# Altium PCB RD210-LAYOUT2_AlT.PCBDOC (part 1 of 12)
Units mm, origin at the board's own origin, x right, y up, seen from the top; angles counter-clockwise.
Board outline 250 x 123 mm, 4 copper layers (TOP, Mid-Layer 1, Mid-Layer 2, BOTTOM), stack 0.711 mm thick; 1043 components, 659 nets, 2786 pads, 1228 vias.
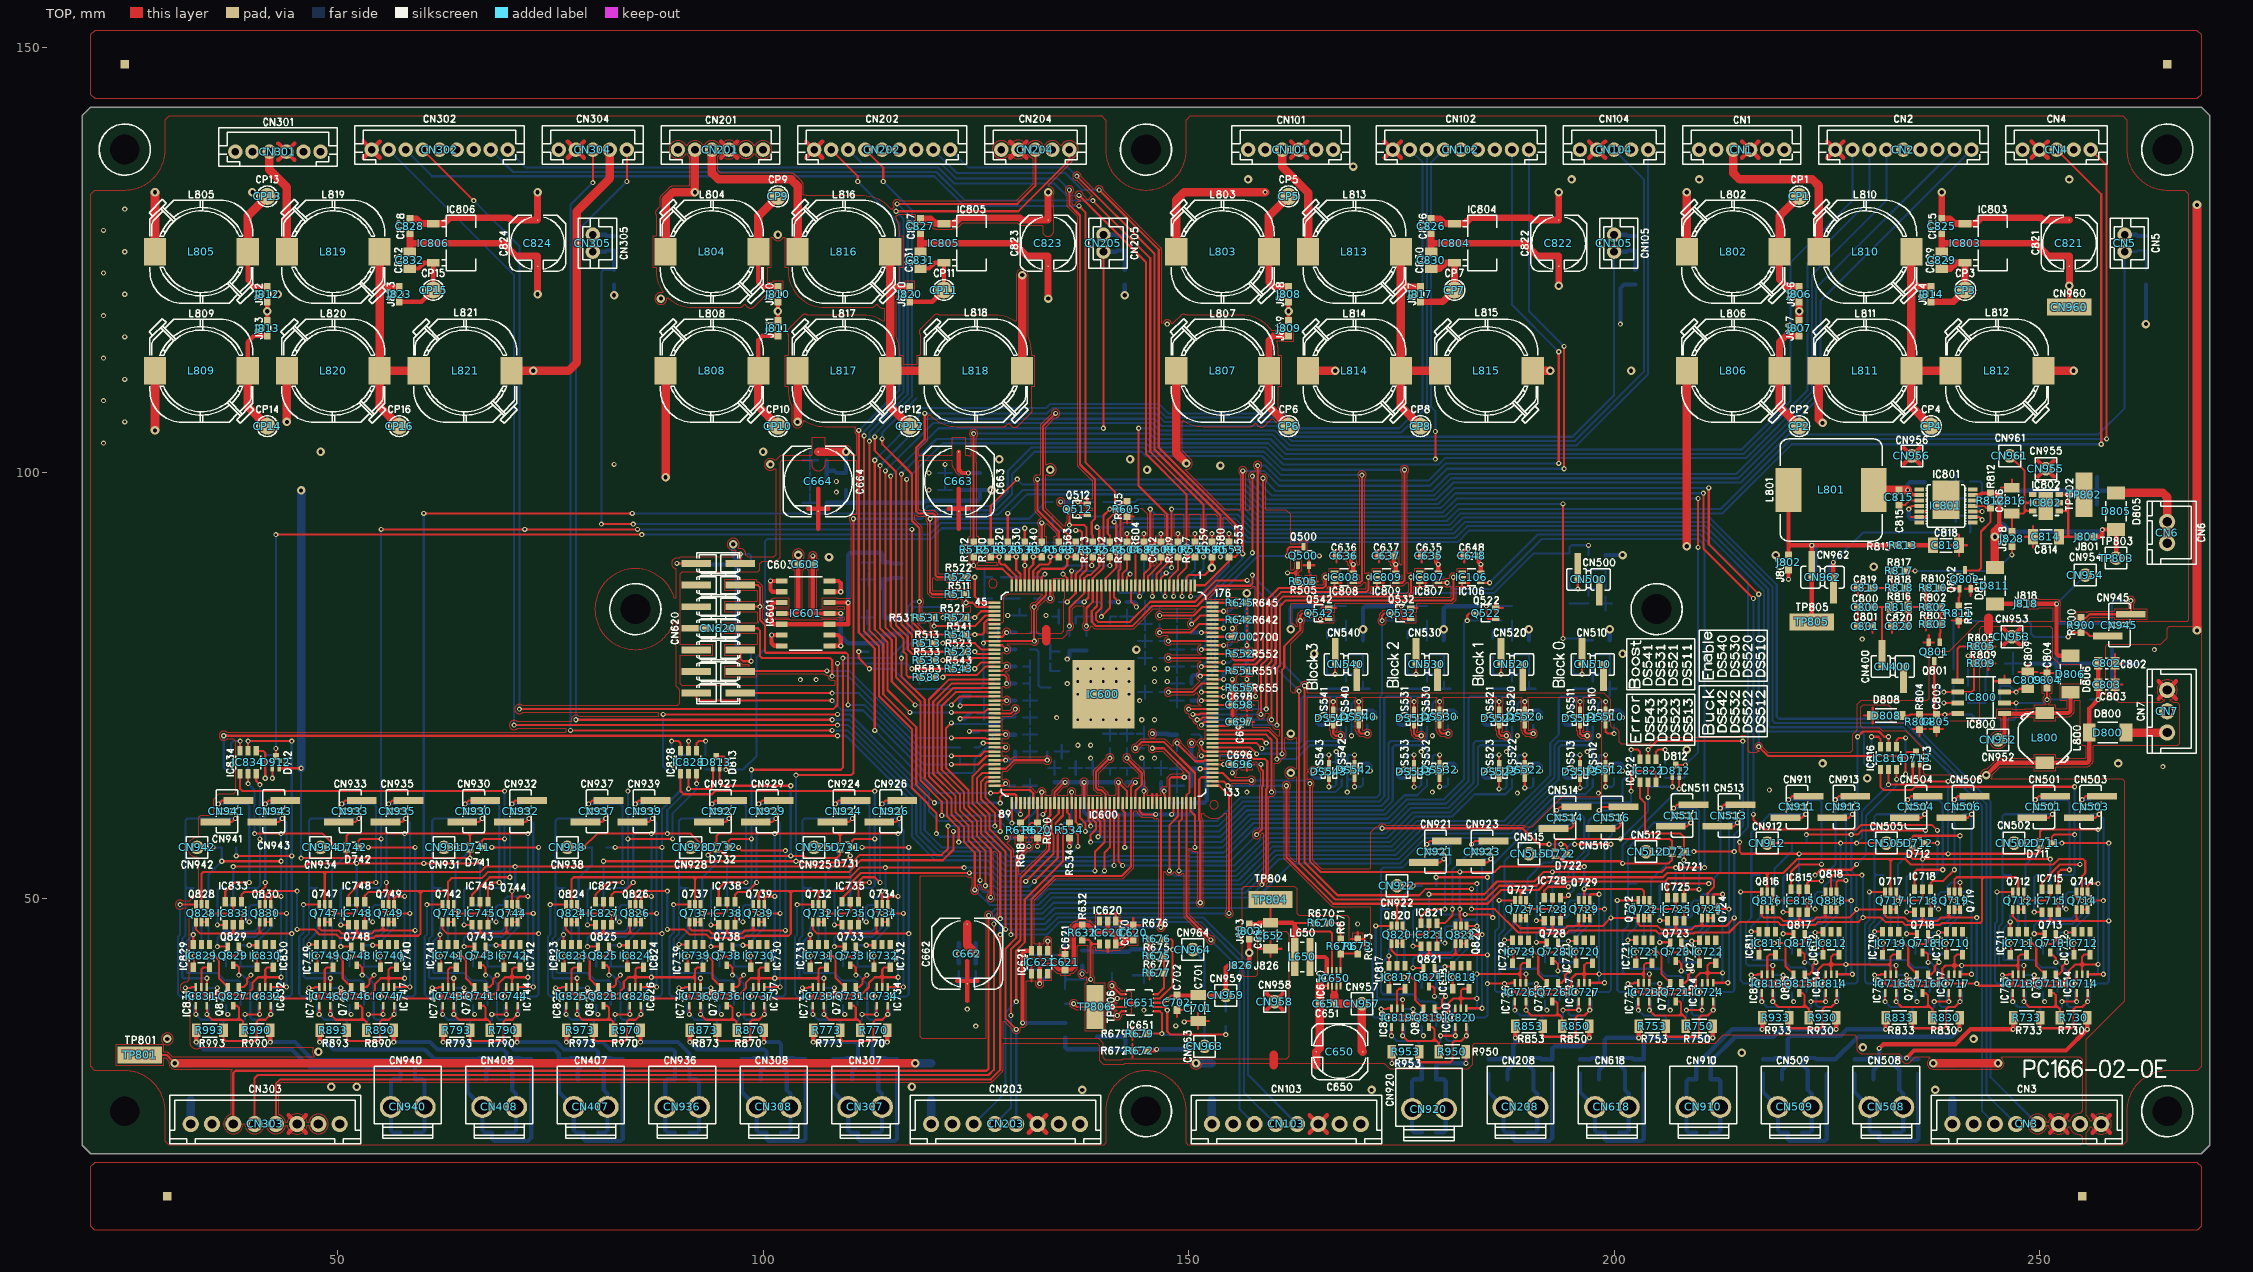
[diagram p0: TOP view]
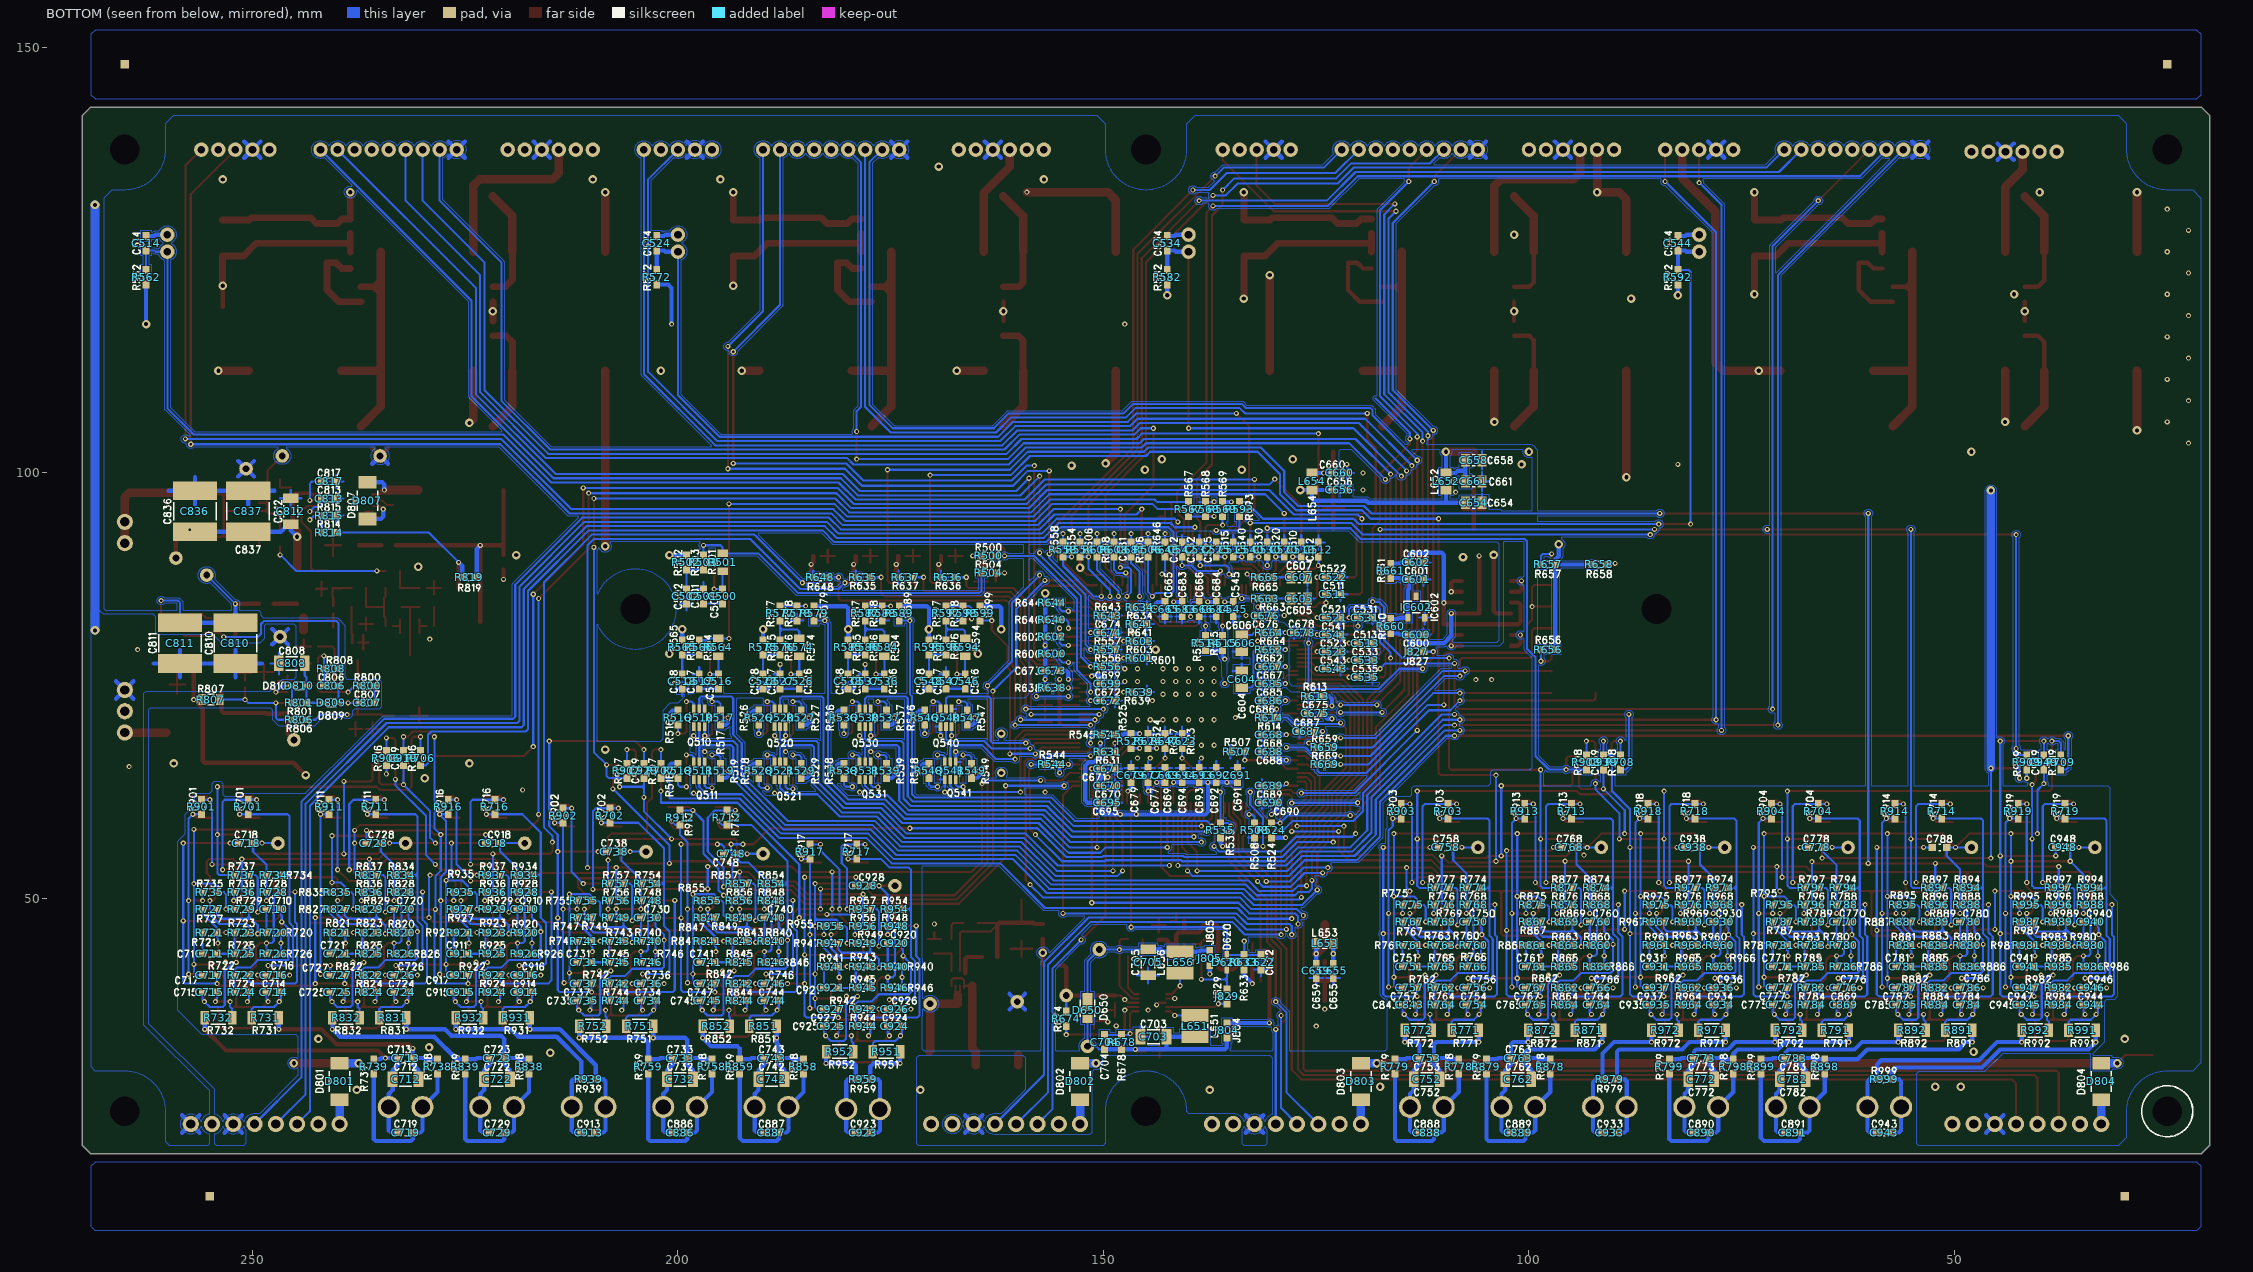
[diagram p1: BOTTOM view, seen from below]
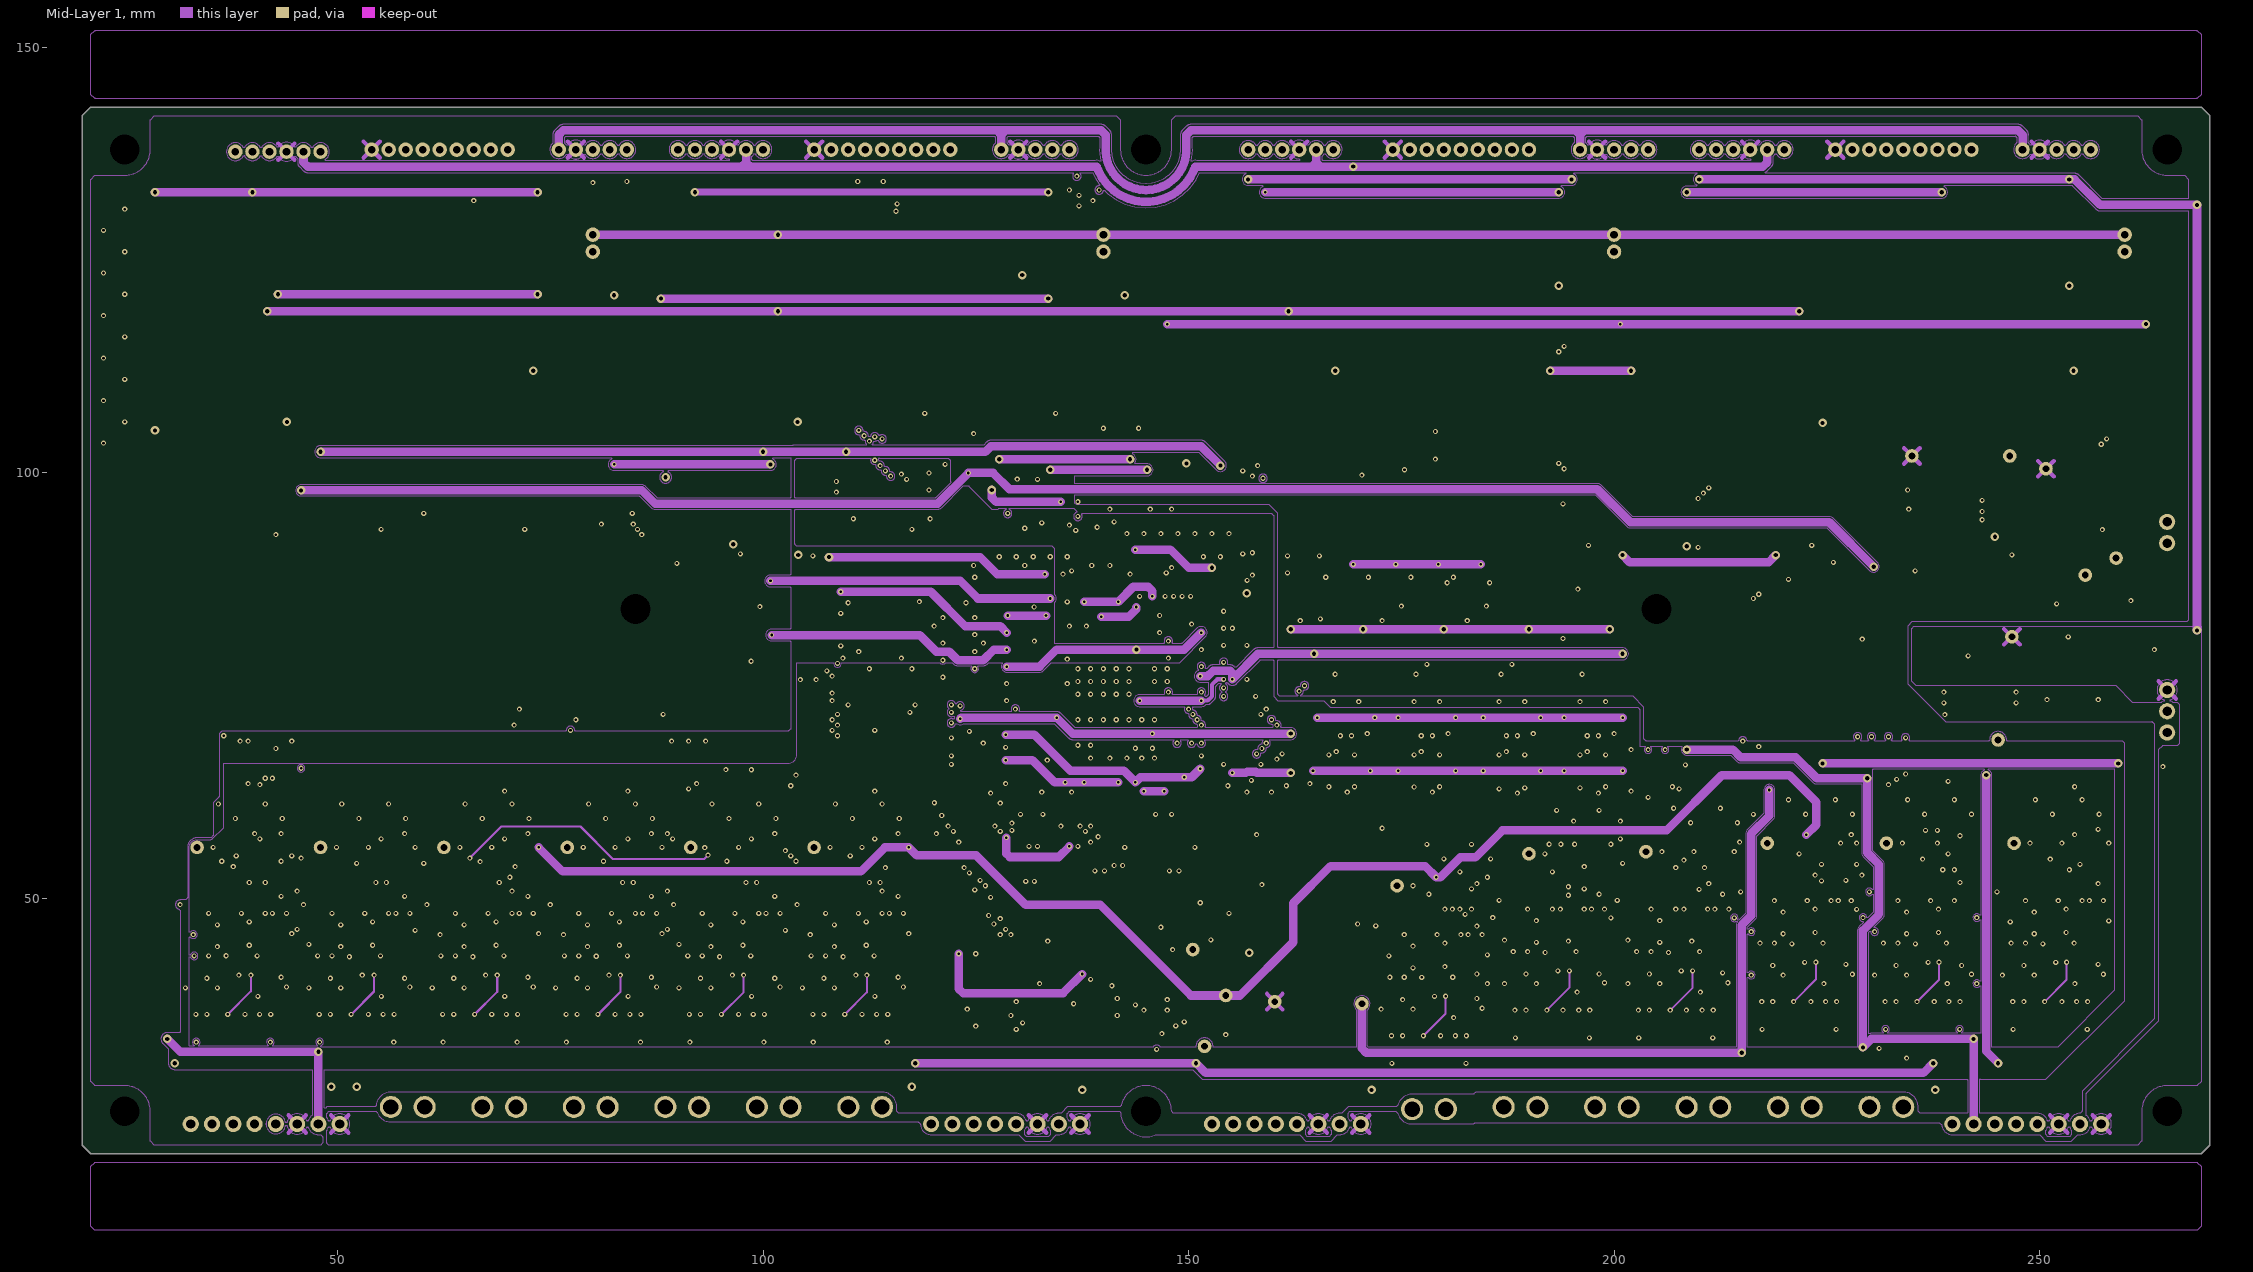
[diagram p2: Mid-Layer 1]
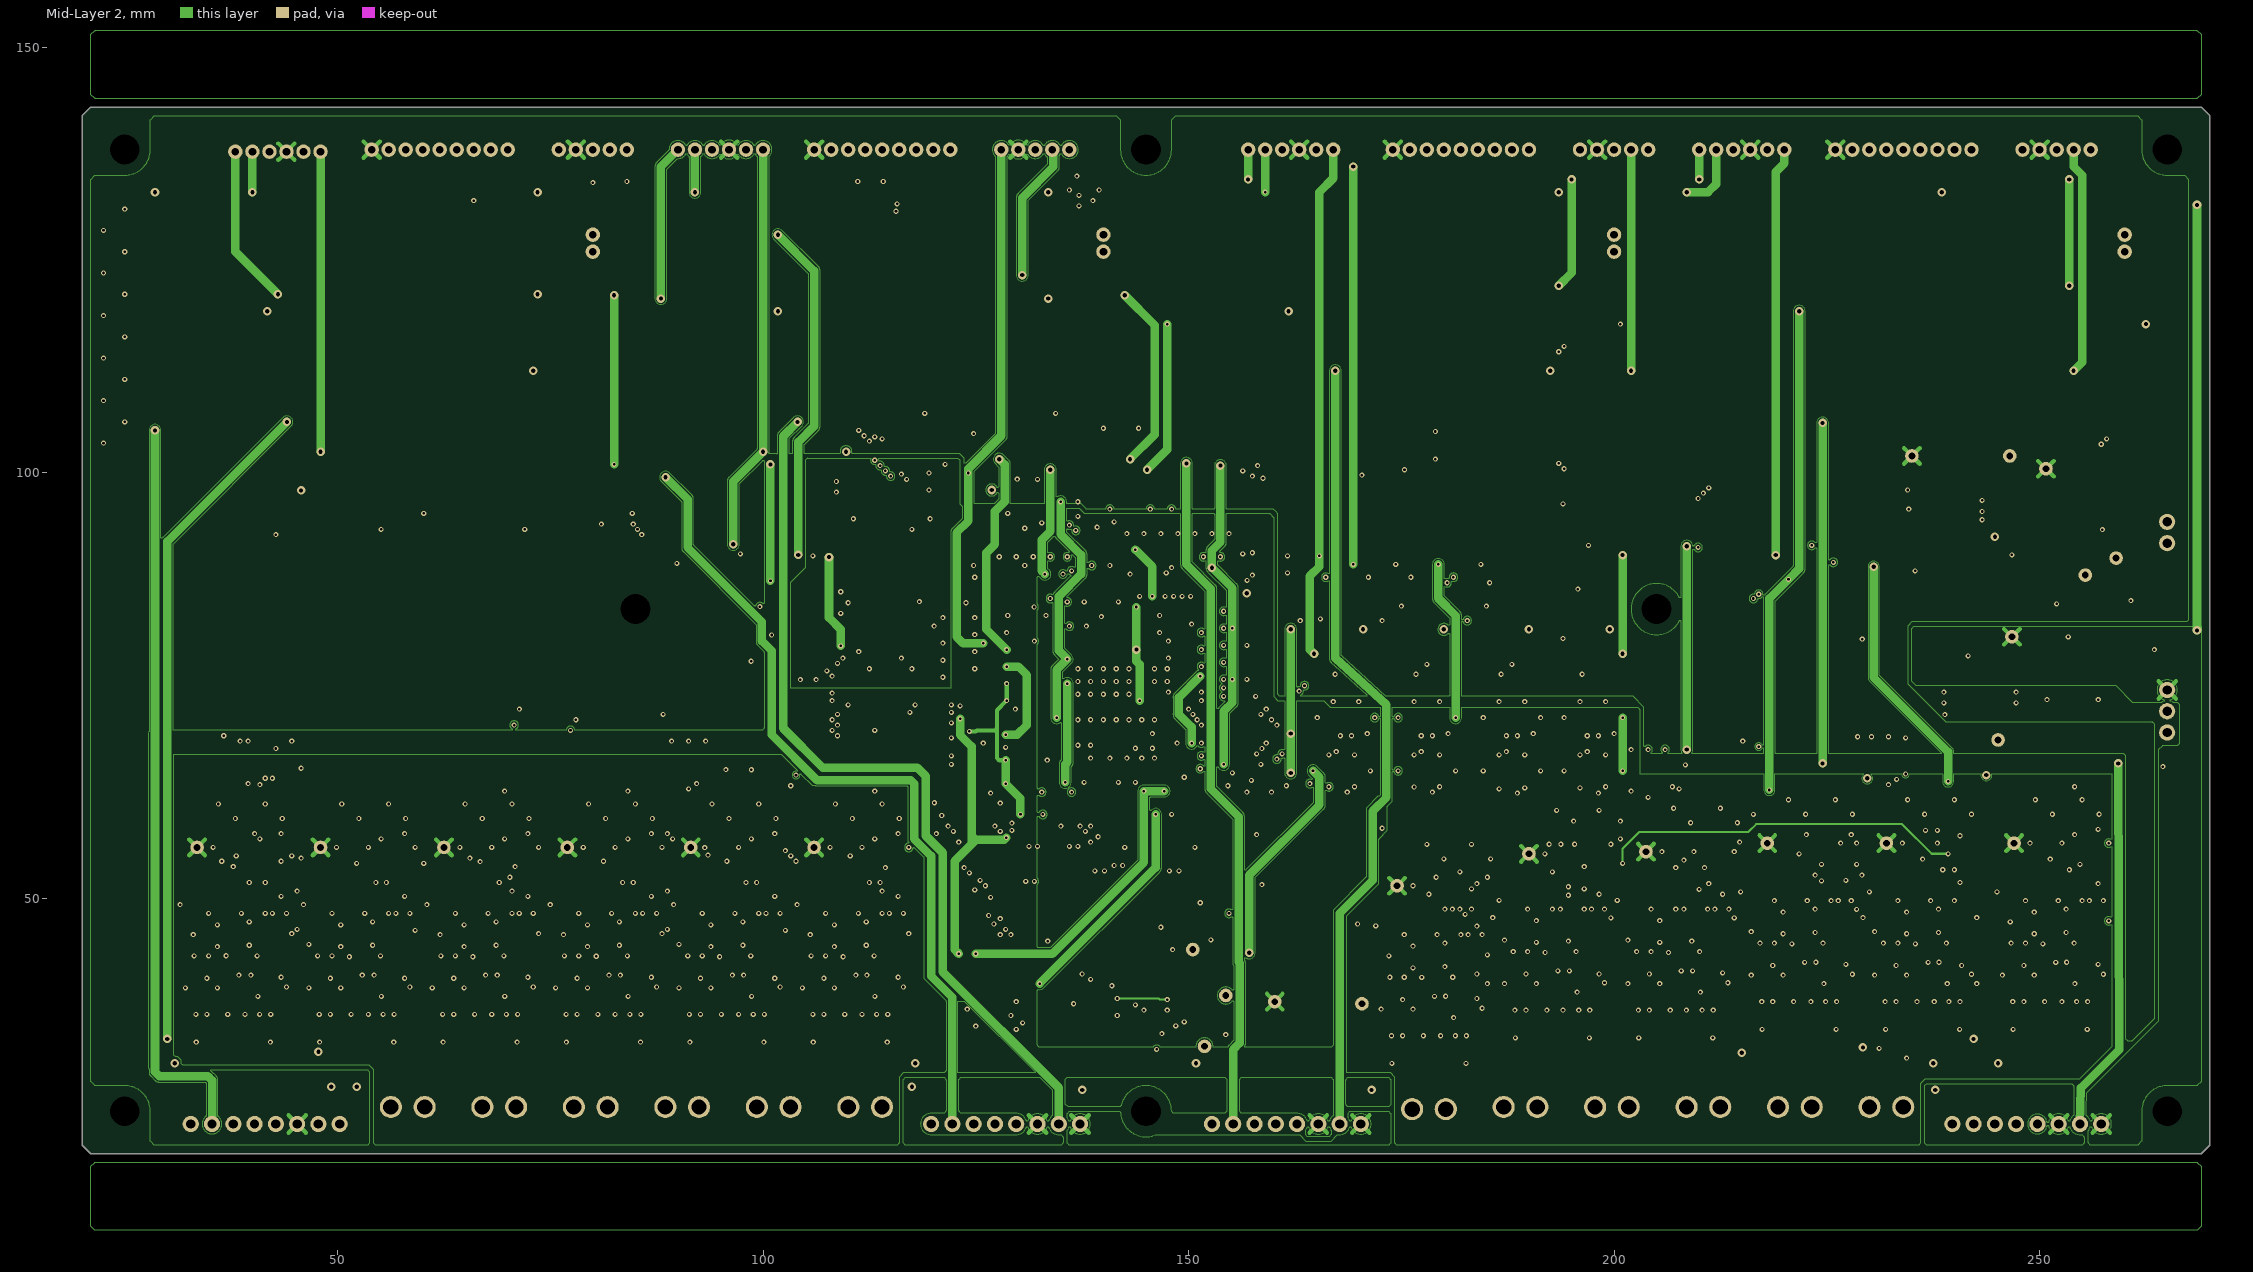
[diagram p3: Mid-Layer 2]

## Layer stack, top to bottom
Top Solder: solder mask 0.0102, Solder Resist, Dk 3.5
TOP: signal copper (thickness not stored)
Mid-Layer 1: signal copper 0.0356
Dielectric2: dielectric 0.32, FR-4, Dk 4.8
Mid-Layer 2: signal copper 0.0356
Dielectric3: dielectric 0.32, FR-4, Dk 4.8
BOTTOM: signal copper (thickness not stored)
Bottom Solder: solder mask 0.0102, Solder Resist, Dk 3.5

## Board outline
21,20 20,21 20,142 21,143 269,143 270,142 270,21 269,20

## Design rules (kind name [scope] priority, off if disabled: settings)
AssemblyTestPointUsage [All] p0: scope1count=1 scope1_0_kind=Board scope1_0_value=Board scope2count=1 scope2_0_kind=Board scope2_0_value=Board commentlength=0
AssemblyTestpoint [All] p0: scope1count=1 scope1_0_kind=Board scope1_0_value=Board scope2count=1 scope2_0_kind=Board scope2_0_value=Board commentlength=0
Clearance [All] p0: scope1count=1 scope1_0_kind=Board scope1_0_value=Board scope2count=1 scope2_0_kind=Board scope2_0_value=Board commentlength=0 gap=0.15
Clearance [All] p1: gap=0.15 ignorepadtopadclearanceinfootprint=TRUE except(0.3: Arc-Hole Track-Hole SMDPad-Hole THPad-Hole Via-Hole Fill-Hole Poly-Hole Region-Hole Text-Hole)
ComponentClearance [All] p0: scope1count=1 scope1_0_kind=Board scope1_0_value=Board scope2count=1 scope2_0_kind=Board scope2_0_value=Board commentlength=0 gap=0.254 collisioncheckmode=3
DiffPairsRouting [All] p0: scope1count=1 scope1_0_kind=Board scope1_0_value=Board scope2count=1 scope2_0_kind=Board scope2_0_value=Board commentlength=0
FabricationTestPointUsage [All] p0: scope1count=1 scope1_0_kind=Board scope1_0_value=Board scope2count=1 scope2_0_kind=Board scope2_0_value=Board commentlength=0 valid=0 allowmultiple=FALSE
FabricationTestpoint [All] p0: scope1count=1 scope1_0_kind=Board scope1_0_value=Board scope2count=1 scope2_0_kind=Board scope2_0_value=Board commentlength=0 side=3 testpointundercomponent=TRUE minsize=1.016 maxsize=2.54 preferedsize=1.524 minholesize=0 maxholesize=1.016 preferedholesize=0.813 testpointgrid=0.025
FanoutControl Fanout_BGA [All] p0 off: scope1count=1 scope1_0_kind=Board scope1_0_value=Board scope2count=1 scope2_0_kind=Board scope2_0_value=Board commentlength=69 // Protel DXP Scope 1 Expression Was: IsBGA   Fanout_BGA (Default Rule)
FanoutControl Fanout_LCC [All] p0 off: scope1count=1 scope1_0_kind=Board scope1_0_value=Board scope2count=1 scope2_0_kind=Board scope2_0_value=Board commentlength=69 // Protel DXP Scope 1 Expression Was: IsLCC   Fanout_LCC (Default Rule)
FanoutControl Fanout_SOIC [All] p0 off: scope1count=1 scope1_0_kind=Board scope1_0_value=Board scope2count=1 scope2_0_kind=Board scope2_0_value=Board commentlength=71 // Protel DXP Scope 1 Expression Was: IsSOIC   Fanout_SOIC (Default Rule)
FanoutControl Fanout_Small [All] p0 off: scope1count=1 scope1_0_kind=Board scope1_0_value=Board scope2count=1 scope2_0_kind=Board scope2_0_value=Board commentlength=84 // Protel DXP Scope 1 Expression Was: (CompPinCount < 5)   Fanout_Small (Default Rule)
FanoutControl Fanout_Default [All] p0: scope1count=1 scope1_0_kind=Board scope1_0_value=Board scope2count=1 scope2_0_kind=Board scope2_0_value=Board commentlength=30 // Fanout_Default (Default Rule)
Height [All] p0: scope1count=1 scope1_0_kind=Board scope1_0_value=Board scope2count=1 scope2_0_kind=Board scope2_0_value=Board commentlength=0
HoleSize [All] p0: scope1count=1 scope1_0_kind=Board scope1_0_value=Board scope2count=1 scope2_0_kind=Board scope2_0_value=Board commentlength=0 absolutevalues=TRUE maxlimit=100 minlimit=0.001 maxpercent=80.000 minpercent=20.000
HoleSize [All] p1: absolutevalues=TRUE maxlimit=100 minlimit=0.001 maxpercent=80.000 minpercent=20.000
HoleToHoleClearance [All] p0: scope1count=1 scope1_0_kind=Board scope1_0_value=Board scope2count=1 scope2_0_kind=Board scope2_0_value=Board commentlength=0
HoleToHoleClearance [All] p1: gap=0.4 allowstackedmicrovias=FALSE
LayerPairs [All] p0: scope1count=1 scope1_0_kind=Board scope1_0_value=Board scope2count=1 scope2_0_kind=Board scope2_0_value=Board commentlength=0 enforce=TRUE
MinimumSolderMaskSliver [All] p0: scope1count=1 scope1_0_kind=Board scope1_0_value=Board scope2count=1 scope2_0_kind=Board scope2_0_value=Board commentlength=0
MinimumSolderMaskSliver [All] p1: minsoldermaskwidth=0.1
NetAntennae [All] p0: scope1count=1 scope1_0_kind=Board scope1_0_value=Board scope2count=1 scope2_0_kind=Board scope2_0_value=Board commentlength=0
NetAntennae [All] p1: netantennaetolerance=100
PasteMaskExpansion [All] p0: scope1count=1 scope1_0_kind=Board scope1_0_value=Board scope2count=1 scope2_0_kind=Board scope2_0_value=Board commentlength=0 expansion=0
PlaneClearance [All] p0: scope1count=1 scope1_0_kind=Board scope1_0_value=Board scope2count=1 scope2_0_kind=Board scope2_0_value=Board commentlength=0 clearance=0.001
PlaneClearance [All] p1: clearance=0.001
PlaneConnect [All] p0: scope1count=1 scope1_0_kind=Board scope1_0_value=Board scope2count=1 scope2_0_kind=Board scope2_0_value=Board commentlength=0 planeconnectstyle=Direct reliefexpansion=0.508 reliefentries=4 reliefconductorwidth=0.254 reliefairgap=0.254
PlaneConnect [All] p1: planeconnectstyle=Direct reliefexpansion=0.508 reliefentries=4 reliefconductorwidth=0.254 reliefairgap=0.254
PolygonConnect [All] p0: scope1count=1 scope1_0_kind=Board scope1_0_value=Board scope2count=1 scope2_0_kind=Board scope2_0_value=Board commentlength=0 connectstyle=Direct reliefconductorwidth=0.254 reliefentries=4 polygonreliefangle="90 Angle"
PolygonConnect [All] p1: connectstyle=Direct reliefconductorwidth=0.254 reliefentries=4 polygonreliefangle="90 Angle" airgapwidth=0.254
RoutingCorners [All] p0: scope1count=1 scope1_0_kind=Board scope1_0_value=Board scope2count=1 scope2_0_kind=Board scope2_0_value=Board commentlength=0 cornerstyle=45-Degree minsetback=2.54 maxsetback=2.54
RoutingLayers [All] p0: scope1count=1 scope1_0_kind=Board scope1_0_value=Board scope2count=1 scope2_0_kind=Board scope2_0_value=Board commentlength=0 top layer=Automatic mid layer 1=Automatic mid layer 2=Automatic bottom layer=Automatic
RoutingPriority [All] p0: scope1count=1 scope1_0_kind=Board scope1_0_value=Board scope2count=1 scope2_0_kind=Board scope2_0_value=Board commentlength=0
RoutingTopology [All] p0: scope1count=1 scope1_0_kind=Board scope1_0_value=Board scope2count=1 scope2_0_kind=Board scope2_0_value=Board commentlength=0 topology=Shortest
RoutingVias [All] p0: scope1count=1 scope1_0_kind=Board scope1_0_value=Board scope2count=1 scope2_0_kind=Board scope2_0_value=Board commentlength=0 holewidth=0.1 width=0.1 viastyle="Through Hole" minholewidth=0.001 minwidth=0.001 maxholewidth=100 maxwidth=100
RoutingVias [All] p1: holewidth=0.1 width=0.1 viastyle="Through Hole" minholewidth=0.001 minwidth=0.001 maxholewidth=100 maxwidth=100
ShortCircuit [All] p0: scope1count=1 scope1_0_kind=Board scope1_0_value=Board scope2count=1 scope2_0_kind=Board scope2_0_value=Board commentlength=0 allowed=FALSE
SilkToBoardRegionClearance [All] p0: scope1count=1 scope1_0_kind=Board scope1_0_value=Board scope2count=1 scope2_0_kind=Board scope2_0_value=Board commentlength=0
SilkToSilkClearance [All] p0: scope1count=1 scope1_0_kind=Board scope1_0_value=Board scope2count=1 scope2_0_kind=Board scope2_0_value=Board commentlength=0
SilkToSilkClearance [All] p1: silktosilkclearance=0.001
SilkToSolderMaskClearance [All] p0 off: scope1count=1 scope1_0_kind=Board scope1_0_value=Board scope2count=1 scope2_0_kind=Board scope2_0_value=Board commentlength=44 // Protel DXP Scope 1 Expression Was: IsPad
SilkToSolderMaskClearance [IsPad] p1: minsilkscreentomaskgap=0 clearancetoexposedcopper=TRUE
SolderMaskExpansion [All] p0: scope1count=1 scope1_0_kind=Board scope1_0_value=Board scope2count=1 scope2_0_kind=Board scope2_0_value=Board commentlength=0 expansion=0.001
SolderMaskExpansion [All] p1: expansion=0.001
UnRoutedNet [All] p0: scope1count=1 scope1_0_kind=Board scope1_0_value=Board scope2count=1 scope2_0_kind=Board scope2_0_value=Board commentlength=0
UnpouredPolygon [All] p0: scope1count=1 scope1_0_kind=Board scope1_0_value=Board scope2count=1 scope2_0_kind=Board scope2_0_value=Board commentlength=0
Width [All] p0: scope1count=1 scope1_0_kind=Board scope1_0_value=Board scope2count=1 scope2_0_kind=Board scope2_0_value=Board commentlength=0 maxlimit=1000 minlimit=2539.975 preferedwidth=0
Width [All] p1: maxlimit=1000 minlimit=2539.975 preferedwidth=0 toplayer_minwidth=0 midlayer1_minwidth=0 midlayer2_minwidth=0 bottomlayer_minwidth=0 minimp=50.000000 maximp=50.000000 favimp=50.000000
22 further rules are at their usual default settings.

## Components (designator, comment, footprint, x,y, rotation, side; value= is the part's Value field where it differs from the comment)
C500 "S2P_CC-1.6x0.8x0.8-PX1.6+65" S2P_CC-1.6x0.8x0.8-PX1.6+65 194.75,85.5 r270 bottom
C501 "S2P_CC-1.6x0.8x0.8-PX1.6+66" S2P_CC-1.6x0.8x0.8-PX1.6+66 197,85.5 r90 bottom
C502 "S2P_CC-1.6x0.8x0.8-PX1.6+67" S2P_CC-1.6x0.8x0.8-PX1.6+67 199,85.5 r270 bottom
C510 "S2P_CC-1.6x0.8x0.8-PX1.6" S2P_CC-1.6x0.8x0.8-PX1.6 126.75,91 r90 bottom
C511 "S2P_CC-1.6x0.8x0.8-PX1.6+1" S2P_CC-1.6x0.8x0.8-PX1.6+1 123,85.75 r0 bottom
C512 "S2P_CC-1.6x0.8x0.8-PX1.6+2" S2P_CC-1.6x0.8x0.8-PX1.6+2 124.75,91 r90 bottom
C513 "S2P_CC-1.6x0.8x0.8-PX1.6+50" S2P_CC-1.6x0.8x0.8-PX1.6+50 119.25,80 r0 bottom
C514 "S2P_CC-1.6x0.8x0.8-PX1.6+90" S2P_CC-1.6x0.8x0.8-PX1.6+90 262.5,127 r90 bottom
C515 "S2P_CC-1.6x0.8x0.8-PX1.6+3" S2P_CC-1.6x0.8x0.8-PX1.6+3 134.75,91 r90 bottom
C516 "S2P_CC-1.6x0.8x0.8-PX1.6+59" S2P_CC-1.6x0.8x0.8-PX1.6+59 195.25,75.5 r270 bottom
C517 "S2P_CC-1.6x0.8x0.8-PX1.6+60" S2P_CC-1.6x0.8x0.8-PX1.6+60 197.5,75.5 r90 bottom
C518 "S2P_CC-1.6x0.8x0.8-PX1.6+61" S2P_CC-1.6x0.8x0.8-PX1.6+61 199.5,75.5 r270 bottom
C520 "S2P_CC-1.6x0.8x0.8-PX1.6+4" S2P_CC-1.6x0.8x0.8-PX1.6+4 128.75,91 r90 bottom
C521 "S2P_CC-1.6x0.8x0.8-PX1.6+5" S2P_CC-1.6x0.8x0.8-PX1.6+5 123,83 r0 bottom
C522 "S2P_CC-1.6x0.8x0.8-PX1.6+6" S2P_CC-1.6x0.8x0.8-PX1.6+6 123,87.75 r0 bottom
C523 "S2P_CC-1.6x0.8x0.8-PX1.6+49" S2P_CC-1.6x0.8x0.8-PX1.6+49 123,79 r0 bottom
C524 "S2P_CC-1.6x0.8x0.8-PX1.6+89" S2P_CC-1.6x0.8x0.8-PX1.6+89 202.5,127 r90 bottom
C525 "S2P_CC-1.6x0.8x0.8-PX1.6+91" S2P_CC-1.6x0.8x0.8-PX1.6+91 136.75,91 r90 bottom
C526 "S2P_CC-1.6x0.8x0.8-PX1.6+68" S2P_CC-1.6x0.8x0.8-PX1.6+68 185.75,75.5 r270 bottom
C527 "S2P_CC-1.6x0.8x0.8-PX1.6+69" S2P_CC-1.6x0.8x0.8-PX1.6+69 188,75.5 r90 bottom
C528 "S2P_CC-1.6x0.8x0.8-PX1.6+70" S2P_CC-1.6x0.8x0.8-PX1.6+70 190,75.5 r270 bottom
C530 "S2P_CC-1.6x0.8x0.8-PX1.6+7" S2P_CC-1.6x0.8x0.8-PX1.6+7 130.75,91 r90 bottom
C531 "S2P_CC-1.6x0.8x0.8-PX1.6+52" S2P_CC-1.6x0.8x0.8-PX1.6+52 119.25,83 r0 bottom
C532 "S2P_CC-1.6x0.8x0.8-PX1.6+8" S2P_CC-1.6x0.8x0.8-PX1.6+8 138.75,91 r90 bottom
C533 "S2P_CC-1.6x0.8x0.8-PX1.6+48" S2P_CC-1.6x0.8x0.8-PX1.6+48 119.25,78 r0 bottom
C534 "S2P_CC-1.6x0.8x0.8-PX1.6+87" S2P_CC-1.6x0.8x0.8-PX1.6+87 142.5,127 r90 bottom
C535 "S2P_CC-1.6x0.8x0.8-PX1.6+92" S2P_CC-1.6x0.8x0.8-PX1.6+92 119.25,76 r0 bottom
C536 "S2P_CC-1.6x0.8x0.8-PX1.6+71" S2P_CC-1.6x0.8x0.8-PX1.6+71 175.75,75.5 r270 bottom
C537 "S2P_CC-1.6x0.8x0.8-PX1.6+72" S2P_CC-1.6x0.8x0.8-PX1.6+72 178,75.5 r90 bottom
C538 "S2P_CC-1.6x0.8x0.8-PX1.6+73" S2P_CC-1.6x0.8x0.8-PX1.6+73 180,75.5 r270 bottom
C540 "S2P_CC-1.6x0.8x0.8-PX1.6+9" S2P_CC-1.6x0.8x0.8-PX1.6+9 132.75,91 r90 bottom
C541 "S2P_CC-1.6x0.8x0.8-PX1.6+51" S2P_CC-1.6x0.8x0.8-PX1.6+51 123,81 r0 bottom
C542 "S2P_CC-1.6x0.8x0.8-PX1.6+10" S2P_CC-1.6x0.8x0.8-PX1.6+10 140.75,91 r90 bottom
C543 "S2P_CC-1.6x0.8x0.8-PX1.6+47" S2P_CC-1.6x0.8x0.8-PX1.6+47 123,77 r0 bottom
C544 "S2P_CC-1.6x0.8x0.8-PX1.6+88" S2P_CC-1.6x0.8x0.8-PX1.6+88 82.5,127 r90 bottom
C545 "S2P_CC-1.6x0.8x0.8-PX1.6+54" S2P_CC-1.6x0.8x0.8-PX1.6+54 134.75,84 r270 bottom
C546 "S2P_CC-1.6x0.8x0.8-PX1.6+62" S2P_CC-1.6x0.8x0.8-PX1.6+62 166.25,75.5 r270 bottom
C547 "S2P_CC-1.6x0.8x0.8-PX1.6+63" S2P_CC-1.6x0.8x0.8-PX1.6+63 168.5,75.5 r90 bottom
C548 "S2P_CC-1.6x0.8x0.8-PX1.6+64" S2P_CC-1.6x0.8x0.8-PX1.6+64 170.5,75.5 r270 bottom
C600 "S2P_CC-1.6x0.8x0.8-PX1.6+76" S2P_CC-1.6x0.8x0.8-PX1.6+76 113.25,81 r180 bottom
C601 "S2P_CC-1.6x0.8x0.8-PX1.6+78" S2P_CC-1.6x0.8x0.8-PX1.6+78 113.25,87.5 r180 bottom
C602 "S2P_CC-1.6x0.8x0.8-PX1.6+77" S2P_CC-1.6x0.8x0.8-PX1.6+77 113.25,89.5 r180 bottom
C603 "S2P_CC-1.6x0.8x0.8-PX1.6+11" S2P_CC-1.6x0.8x0.8-PX1.6+11 105,89.25 r0 top
C604 "S2P_CC-2x1.25x1.25-PX2" S2P_CC-2x1.25x1.25-PX2 133.75,75.75 r270 bottom
C605 "S2P_CC-2x1.25x1.25-PX2+3" S2P_CC-2x1.25x1.25-PX2+3 127,85.25 r180 bottom
C606 "S2P_CC-2x1.25x1.25-PX2+1" S2P_CC-2x1.25x1.25-PX2+1 133.75,80 r90 bottom
C607 "S2P_CC-2x1.25x1.25-PX2+2" S2P_CC-2x1.25x1.25-PX2+2 127,87.75 r180 bottom
C620 "S2P_CC-1.6x0.8x0.8-PX1.6+12" S2P_CC-1.6x0.8x0.8-PX1.6+12 143.5,46 r90 top
C621 "S2P_CC-1.6x0.8x0.8-PX1.6+80" S2P_CC-1.6x0.8x0.8-PX1.6+80 135.5,42.5 r90 top
C622 "S2P_CC-1.6x0.8x0.8-PX1.6+13" S2P_CC-1.6x0.8x0.8-PX1.6+13 131.5,42.5 r270 bottom
C635 "S2P_CC-1.6x0.8x0.8-PX1.6+93" S2P_CC-1.6x0.8x0.8-PX1.6+93 178.25,90.25 r0 top
C636 "S2P_CC-1.6x0.8x0.8-PX1.6+94" S2P_CC-1.6x0.8x0.8-PX1.6+94 168.25,90.25 r0 top
C637 "S2P_CC-1.6x0.8x0.8-PX1.6+95" S2P_CC-1.6x0.8x0.8-PX1.6+95 173.25,90.25 r0 top
C648 "S2P_CC-1.6x0.8x0.8-PX1.6+14" S2P_CC-1.6x0.8x0.8-PX1.6+14 183.25,90.25 r0 top
C650 "S2P_CE-6.6x6.6x5.8-PX7+4" S2P_CE-6.6x6.6x5.8-PX7+4 167.75,32 r180 top
C651 "S2P_CC-1.6x0.8x0.8-PX1.6+15" S2P_CC-1.6x0.8x0.8-PX1.6+15 166.25,37.625 r0 top
C652 "_CGA5L1X7R0J226M160AC_+2" _CGA5L1X7R0J226M160AC_+2 159.625,45.625 r90 top
C654 "S2P_CC-2x1.25x1.25-PX2+11" S2P_CC-2x1.25x1.25-PX2+11 106.5,96.5 r180 bottom
C655 "S2P_CC-1.6x0.8x0.8-PX1.6+74" S2P_CC-1.6x0.8x0.8-PX1.6+74 123,41.5 r270 bottom
C656 "S2P_CC-1.6x0.8x0.8-PX1.6+86" S2P_CC-1.6x0.8x0.8-PX1.6+86 122.25,98 r180 bottom
C658 "S2P_CC-2x1.25x1.25-PX2+10" S2P_CC-2x1.25x1.25-PX2+10 106.5,101.5 r180 bottom
C659 "S2P_CC-1.6x0.8x0.8-PX1.6+75" S2P_CC-1.6x0.8x0.8-PX1.6+75 125,41.5 r270 bottom
C660 "S2P_CC-1.6x0.8x0.8-PX1.6+85" S2P_CC-1.6x0.8x0.8-PX1.6+85 122.25,100 r180 bottom
C661 "S2P_CC-2x1.25x1.25-PX2+9" S2P_CC-2x1.25x1.25-PX2+9 106.5,99 r180 bottom
C662 "S2P_CE-8.3x8.3x10-PX8.9" S2P_CE-8.3x8.3x10-PX8.9 124,43.5 r270 top
C663 "S2P_CE-8.3x8.3x10-PX8.9+1" S2P_CE-8.3x8.3x10-PX8.9+1 123,99 r270 top
C664 "S2P_CE-8.3x8.3x10-PX8.9+2" S2P_CE-8.3x8.3x10-PX8.9+2 106.5,99 r270 top
C665 "S2P_CC-1.6x0.8x0.8-PX1.6+58" S2P_CC-1.6x0.8x0.8-PX1.6+58 142.75,84 r270 bottom
C666 "S2P_CC-1.6x0.8x0.8-PX1.6+56" S2P_CC-1.6x0.8x0.8-PX1.6+56 138.75,84 r270 bottom
C667 "S2P_CC-1.6x0.8x0.8-PX1.6+42" S2P_CC-1.6x0.8x0.8-PX1.6+42 130.5,77.25 r180 bottom
C668 "S2P_CC-1.6x0.8x0.8-PX1.6+41" S2P_CC-1.6x0.8x0.8-PX1.6+41 130.5,69.25 r180 bottom
C669 "S2P_CC-1.6x0.8x0.8-PX1.6+33" S2P_CC-1.6x0.8x0.8-PX1.6+33 142.75,64.5 r270 bottom
C670 "S2P_CC-1.6x0.8x0.8-PX1.6+30" S2P_CC-1.6x0.8x0.8-PX1.6+30 149.5,63.25 r0 bottom
C671 "S2P_CC-1.6x0.8x0.8-PX1.6+28" S2P_CC-1.6x0.8x0.8-PX1.6+28 149.5,65.25 r180 bottom
C672 "S2P_CC-1.6x0.8x0.8-PX1.6+26" S2P_CC-1.6x0.8x0.8-PX1.6+26 149.5,73.25 r180 bottom
C673 "S2P_CC-1.6x0.8x0.8-PX1.6+25" S2P_CC-1.6x0.8x0.8-PX1.6+25 156,76.75 r0 bottom
C674 "S2P_CC-1.6x0.8x0.8-PX1.6+22" S2P_CC-1.6x0.8x0.8-PX1.6+22 149.5,81.25 r180 bottom
C675 "S2P_CC-1.6x0.8x0.8-PX1.6+44" S2P_CC-1.6x0.8x0.8-PX1.6+44 125.125,71.75 r180 bottom
C676 "S2P_CC-1.6x0.8x0.8-PX1.6+53" S2P_CC-1.6x0.8x0.8-PX1.6+53 131,83.25 r180 bottom
C677 "S2P_CC-1.6x0.8x0.8-PX1.6+32" S2P_CC-1.6x0.8x0.8-PX1.6+32 144.75,64.5 r270 bottom
C678 "S2P_CC-1.6x0.8x0.8-PX1.6+79" S2P_CC-1.6x0.8x0.8-PX1.6+79 126.75,81.25 r180 bottom
C679 "S2P_CC-1.6x0.8x0.8-PX1.6+31" S2P_CC-1.6x0.8x0.8-PX1.6+31 146.75,64.5 r270 bottom
C680 "S2P_CC-1.6x0.8x0.8-PX1.6+16" S2P_CC-1.6x0.8x0.8-PX1.6+16 152.75,91 r270 top
C681 "S2P_CC-1.6x0.8x0.8-PX1.6+17" S2P_CC-1.6x0.8x0.8-PX1.6+17 146.75,91 r90 bottom
C682 "S2P_CC-1.6x0.8x0.8-PX1.6+18" S2P_CC-1.6x0.8x0.8-PX1.6+18 144.75,91 r270 top
C683 "S2P_CC-1.6x0.8x0.8-PX1.6+57" S2P_CC-1.6x0.8x0.8-PX1.6+57 140.75,84 r270 bottom
C684 "S2P_CC-1.6x0.8x0.8-PX1.6+55" S2P_CC-1.6x0.8x0.8-PX1.6+55 136.75,84 r270 bottom
C685 "S2P_CC-1.6x0.8x0.8-PX1.6+46" S2P_CC-1.6x0.8x0.8-PX1.6+46 130.5,75.25 r180 bottom
C686 "S2P_CC-1.6x0.8x0.8-PX1.6+45" S2P_CC-1.6x0.8x0.8-PX1.6+45 130.5,73.25 r180 bottom
C687 "S2P_CC-1.6x0.8x0.8-PX1.6+43" S2P_CC-1.6x0.8x0.8-PX1.6+43 126.125,69.625 r180 bottom
C688 "S2P_CC-1.6x0.8x0.8-PX1.6+40" S2P_CC-1.6x0.8x0.8-PX1.6+40 130.5,67.25 r180 bottom
C689 "S2P_CC-1.6x0.8x0.8-PX1.6+39" S2P_CC-1.6x0.8x0.8-PX1.6+39 130.5,63.25 r180 bottom
C690 "S2P_CC-1.6x0.8x0.8-PX1.6+38" S2P_CC-1.6x0.8x0.8-PX1.6+38 130.5,61.25 r180 bottom
C691 "S2P_CC-1.6x0.8x0.8-PX1.6+37" S2P_CC-1.6x0.8x0.8-PX1.6+37 134.25,64.5 r270 bottom
C692 "S2P_CC-1.6x0.8x0.8-PX1.6+36" S2P_CC-1.6x0.8x0.8-PX1.6+36 136.75,64.5 r270 bottom
C693 "S2P_CC-1.6x0.8x0.8-PX1.6+35" S2P_CC-1.6x0.8x0.8-PX1.6+35 138.75,64.5 r270 bottom
C694 "S2P_CC-1.6x0.8x0.8-PX1.6+34" S2P_CC-1.6x0.8x0.8-PX1.6+34 140.75,64.5 r270 bottom
C695 "S2P_CC-1.6x0.8x0.8-PX1.6+29" S2P_CC-1.6x0.8x0.8-PX1.6+29 149.5,61.25 r180 bottom
C696 "S2P_CC-1.6x0.8x0.8-PX1.6+27" S2P_CC-1.6x0.8x0.8-PX1.6+27 156,65.75 r180 top
C697 "S2P_CC-1.6x0.8x0.8-PX1.6+19" S2P_CC-1.6x0.8x0.8-PX1.6+19 156,70.75 r180 top
C698 "S2P_CC-1.6x0.8x0.8-PX1.6+20" S2P_CC-1.6x0.8x0.8-PX1.6+20 156,72.75 r180 top
C699 "S2P_CC-1.6x0.8x0.8-PX1.6+24" S2P_CC-1.6x0.8x0.8-PX1.6+24 149.5,75.25 r180 bottom
C700 "S2P_CC-1.6x0.8x0.8-PX1.6+23" S2P_CC-1.6x0.8x0.8-PX1.6+23 156,80.75 r180 top
C701 "_CGA5L1X7R1H106K160AC_+3" _CGA5L1X7R1H106K160AC_+3 151.125,37.125 r90 top
C702 "S2P_CC-1.6x0.8x0.8-PX1.6+21" S2P_CC-1.6x0.8x0.8-PX1.6+21 148.625,37.75 r90 top
C703 "_CGA5L1X7R0J226M160AC_+1" _CGA5L1X7R0J226M160AC_+1 144.125,33.75 r0 bottom
C704 "S2P_CC-1.6x0.8x0.8-PX1.6+106" S2P_CC-1.6x0.8x0.8-PX1.6+106 149.875,33.125 r90 bottom
C705 "_CGA5L1X7R0J226M160AC_" _CGA5L1X7R0J226M160AC_ 144.75,42.5 r270 bottom
C710 "_CGA3E2X7R1H104K080AA_+2" _CGA3E2X7R1H104K080AA_+2 247.5,48.75 r0 bottom
C711 "_CGA3E2X7R1H104K080AA_+4" _CGA3E2X7R1H104K080AA_+4 255,43.5 r0 bottom
C712 "_CGA5H2C0G1H473J115AA_" _CGA5H2C0G1H473J115AA_ 232,28.75 r0 bottom
C713 "_CGA3E2C0G1H472J080AA_+7" _CGA3E2C0G1H472J080AA_+7 232,31.25 r0 bottom
C714 "_CGA3E2C0G1H472J080AA_+2" _CGA3E2C0G1H472J080AA_+2 247.5,39 r0 bottom
C715 "_CGA3E2C0G1H472J080AA_+1" _CGA3E2C0G1H472J080AA_+1 255,39 r0 bottom
C716 "_CGA3E2X7R1H104K080AA_+1" _CGA3E2X7R1H104K080AA_+1 247.5,41 r180 bottom
C717 "_CGA3E2X7R1H104K080AA_" _CGA3E2X7R1H104K080AA_ 255,41 r180 bottom
C718 "_CGA3E2X7R1H104K080AA_+3" _CGA3E2X7R1H104K080AA_+3 250.75,56.5 r0 bottom
C719 "_CGA3E2C0G1H472J080AA_" _CGA3E2C0G1H472J080AA_ 232,22.5 r0 bottom
C720 "_CGA3E2X7R1H104K080AA_+14" _CGA3E2X7R1H104K080AA_+14 232.5,48.75 r0 bottom
C721 "_CGA3E2X7R1H104K080AA_+13" _CGA3E2X7R1H104K080AA_+13 240,43.5 r0 bottom
C722 "_CGA5H2C0G1H473J115AA_+2" _CGA5H2C0G1H473J115AA_+2 221.25,28.75 r0 bottom
C723 "_CGA3E2C0G1H472J080AA_+9" _CGA3E2C0G1H472J080AA_+9 221.25,31.25 r0 bottom
C724 "_CGA3E2C0G1H472J080AA_+10" _CGA3E2C0G1H472J080AA_+10 232.5,39 r0 bottom
C725 "_CGA3E2C0G1H472J080AA_+11" _CGA3E2C0G1H472J080AA_+11 240,39 r0 bottom
C726 "_CGA3E2X7R1H104K080AA_+11" _CGA3E2X7R1H104K080AA_+11 232.5,41 r180 bottom
C727 "_CGA3E2X7R1H104K080AA_+12" _CGA3E2X7R1H104K080AA_+12 240,41 r180 bottom
C728 "_CGA3E2X7R1H104K080AA_+15" _CGA3E2X7R1H104K080AA_+15 235.75,56.5 r0 bottom
C729 "_CGA3E2C0G1H472J080AA_+8" _CGA3E2C0G1H472J080AA_+8 221.25,22.5 r0 bottom
C730 "_CGA3E2X7R1H104K080AA_+7" _CGA3E2X7R1H104K080AA_+7 203.5,47.75 r0 bottom
C731 "_CGA3E2X7R1H104K080AA_+9" _CGA3E2X7R1H104K080AA_+9 211,42.5 r0 bottom
C732 "_CGA5H2C0G1H473J115AA_+1" _CGA5H2C0G1H473J115AA_+1 199.75,28.75 r0 bottom
C733 "_CGA3E2C0G1H472J080AA_+4" _CGA3E2C0G1H472J080AA_+4 199.75,31.25 r0 bottom
C734 "_CGA3E2C0G1H472J080AA_+5" _CGA3E2C0G1H472J080AA_+5 203.5,38 r0 bottom
C735 "_CGA3E2C0G1H472J080AA_+6" _CGA3E2C0G1H472J080AA_+6 211,38 r0 bottom
C736 "_CGA3E2X7R1H104K080AA_+6" _CGA3E2X7R1H104K080AA_+6 203.5,40 r180 bottom
C737 "_CGA3E2X7R1H104K080AA_+8" _CGA3E2X7R1H104K080AA_+8 211,40 r180 bottom
C738 "_CGA3E2X7R1H104K080AA_+5" _CGA3E2X7R1H104K080AA_+5 207.5,55.5 r0 bottom
C740 "_CGA3E2X7R1H104K080AA_+24" _CGA3E2X7R1H104K080AA_+24 189,47.75 r0 bottom
C741 "_CGA3E2X7R1H104K080AA_+10" _CGA3E2X7R1H104K080AA_+10 196.5,42.5 r0 bottom
C742 "_CGA5H2C0G1H473J115AA_+3" _CGA5H2C0G1H473J115AA_+3 189,28.75 r0 bottom
C743 "_CGA3E2C0G1H472J080AA_+16" _CGA3E2C0G1H472J080AA_+16 189,31.25 r0 bottom
C744 "_CGA3E2C0G1H472J080AA_+17" _CGA3E2C0G1H472J080AA_+17 189,38 r0 bottom
C745 "_CGA3E2C0G1H472J080AA_+18" _CGA3E2C0G1H472J080AA_+18 196.5,38 r0 bottom
C746 "_CGA3E2X7R1H104K080AA_+22" _CGA3E2X7R1H104K080AA_+22 189,40 r180 bottom
C747 "_CGA3E2X7R1H104K080AA_+23" _CGA3E2X7R1H104K080AA_+23 196.5,40 r180 bottom
C748 "_CGA3E2X7R1H104K080AA_+25" _CGA3E2X7R1H104K080AA_+25 193.75,55.25 r0 bottom
C750 "_CGA3E2X7R1H104K080AA_+33" _CGA3E2X7R1H104K080AA_+33 106.5,47.25 r0 bottom
C751 "_CGA3E2X7R1H104K080AA_+34" _CGA3E2X7R1H104K080AA_+34 114,42 r0 bottom
C752 "_CGA5H2C0G1H473J115AA_+4" _CGA5H2C0G1H473J115AA_+4 112,28.75 r0 bottom
C753 "_CGA3E2C0G1H472J080AA_+23" _CGA3E2C0G1H472J080AA_+23 112,31.25 r0 bottom
C754 "_CGA3E2C0G1H472J080AA_+24" _CGA3E2C0G1H472J080AA_+24 106.5,37.5 r0 bottom
C756 "_CGA3E2X7R1H104K080AA_+31" _CGA3E2X7R1H104K080AA_+31 106.5,39.5 r180 bottom
C757 "_CGA3E2X7R1H104K080AA_+32" _CGA3E2X7R1H104K080AA_+32 114,39.5 r180 bottom
C758 "_CGA3E2X7R1H104K080AA_+35" _CGA3E2X7R1H104K080AA_+35 109.75,56 r0 bottom
C760 "_CGA3E2X7R1H104K080AA_+42" _CGA3E2X7R1H104K080AA_+42 92,47.25 r0 bottom
C761 "_CGA3E2X7R1H104K080AA_+44" _CGA3E2X7R1H104K080AA_+44 99.5,42 r0 bottom
C762 "_CGA5H2C0G1H473J115AA_+6" _CGA5H2C0G1H473J115AA_+6 101.25,28.75 r0 bottom
C763 "_CGA3E2C0G1H472J080AA_+31" _CGA3E2C0G1H472J080AA_+31 101.25,31.25 r0 bottom
C764 "_CGA3E2C0G1H472J080AA_+32" _CGA3E2C0G1H472J080AA_+32 92,37.5 r0 bottom
C765 "_CGA3E2C0G1H472J080AA_+33" _CGA3E2C0G1H472J080AA_+33 99.5,37.5 r0 bottom
C766 "_CGA3E2X7R1H104K080AA_+41" _CGA3E2X7R1H104K080AA_+41 92,39.5 r180 bottom
C767 "_CGA3E2X7R1H104K080AA_+43" _CGA3E2X7R1H104K080AA_+43 99.5,39.5 r180 bottom
C768 "_CGA3E2X7R1H104K080AA_+45" _CGA3E2X7R1H104K080AA_+45 95.25,56 r0 bottom
C770 "_CGA3E2X7R1H104K080AA_+37" _CGA3E2X7R1H104K080AA_+37 63,47.25 r0 bottom
C771 "_CGA3E2X7R1H104K080AA_+39" _CGA3E2X7R1H104K080AA_+39 70.5,42 r0 bottom
C772 "_CGA5H2C0G1H473J115AA_+5" _CGA5H2C0G1H473J115AA_+5 79.75,28.75 r0 bottom
C773 "_CGA3E2C0G1H472J080AA_+27" _CGA3E2C0G1H472J080AA_+27 79.75,31.25 r0 bottom
C775 "_CGA3E2C0G1H472J080AA_+29" _CGA3E2C0G1H472J080AA_+29 70.5,37.5 r0 bottom
C776 "_CGA3E2X7R1H104K080AA_+36" _CGA3E2X7R1H104K080AA_+36 63,39.5 r180 bottom
C777 "_CGA3E2X7R1H104K080AA_+38" _CGA3E2X7R1H104K080AA_+38 70.5,39.5 r180 bottom
C778 "_CGA3E2X7R1H104K080AA_+40" _CGA3E2X7R1H104K080AA_+40 66.25,56 r0 bottom
C780 "_CGA3E2X7R1H104K080AA_+53" _CGA3E2X7R1H104K080AA_+53 48.5,47.25 r0 bottom
C781 "_CGA3E2X7R1H104K080AA_+55" _CGA3E2X7R1H104K080AA_+55 56,42 r0 bottom
C782 "_CGA5H2C0G1H473J115AA_+7" _CGA5H2C0G1H473J115AA_+7 69,28.75 r0 bottom
C783 "_CGA3E2C0G1H472J080AA_+38" _CGA3E2C0G1H472J080AA_+38 69,31.25 r0 bottom
C784 "_CGA3E2C0G1H472J080AA_+39" _CGA3E2C0G1H472J080AA_+39 48.5,37.5 r0 bottom
C785 "_CGA3E2C0G1H472J080AA_+40" _CGA3E2C0G1H472J080AA_+40 56,37.5 r0 bottom
C786 "_CGA3E2X7R1H104K080AA_+52" _CGA3E2X7R1H104K080AA_+52 48.5,39.5 r180 bottom
C787 "_CGA3E2X7R1H104K080AA_+54" _CGA3E2X7R1H104K080AA_+54 56,39.5 r180 bottom
C800 "S2P_CC-1.6x0.8x0.8-PX1.6+103" S2P_CC-1.6x0.8x0.8-PX1.6+103 229.5,84.25 r0 top
C801 "S2P_CC-1.6x0.8x0.8-PX1.6+104" S2P_CC-1.6x0.8x0.8-PX1.6+104 229.5,82 r180 top
C802 "S2P_CC-2x1.25x1.25-PX2+12" S2P_CC-2x1.25x1.25-PX2+12 257.875,77.625 r180 top
C803 "S2P_CC-2x1.25x1.25-PX2+4" S2P_CC-2x1.25x1.25-PX2+4 257.875,75.125 r180 top
C804 "S2P_CC-1.6x0.8x0.8-PX1.6+96" S2P_CC-1.6x0.8x0.8-PX1.6+96 250.875,75.625 r270 top
C805 "S2P_CC-1.6x0.8x0.8-PX1.6+99" S2P_CC-1.6x0.8x0.8-PX1.6+99 237.875,70.75 r270 top
C806 "S2P_CC-1.6x0.8x0.8-PX1.6+105" S2P_CC-1.6x0.8x0.8-PX1.6+105 240.75,75 r0 bottom
C807 "S2P_CC-1.6x0.8x0.8-PX1.6+100" S2P_CC-1.6x0.8x0.8-PX1.6+100 236.5,73 r180 bottom
C808 "_CGA5L1X7R1H106K160AC_+2" _CGA5L1X7R1H106K160AC_+2 245.375,77.625 r0 bottom
C809 "S2P_CC-2x1.25x1.25-PX2+13" S2P_CC-2x1.25x1.25-PX2+13 248.625,75.625 r270 top
C810 "_CKG57NX7S2A226M500JJ_+1" _CKG57NX7S2A226M500JJ_+1 252,80 r270 bottom
C811 "_CKG57NX7S2A226M500JJ_+2" _CKG57NX7S2A226M500JJ_+2 258.5,80 r270 bottom
C812 "_CGA5L2X7R2A104K160AA_+1" _CGA5L2X7R2A104K160AA_+1 245.5,95.5 r90 bottom
C813 "S2P_CC-1.6x0.8x0.8-PX1.6+98" S2P_CC-1.6x0.8x0.8-PX1.6+98 241,97 r180 bottom
C814 "_CGA5L2X7R2A104K160AA_" _CGA5L2X7R2A104K160AA_ 250.75,92.5 r180 top
C815 "_CEU3E2X7R1H223K080AE_" _CEU3E2X7R1H223K080AE_ 233.5,97.125 r90 top
C816 "_CGA5L1X7R1H106K160AC_" _CGA5L1X7R1H106K160AC_ 246.75,96.75 r270 top
C817 "S2P_CC-1.6x0.8x0.8-PX1.6+97" S2P_CC-1.6x0.8x0.8-PX1.6+97 241,99 r180 bottom
C818 "_CGA5L1X7R1H106K160AC_+1" _CGA5L1X7R1H106K160AC_+1 239,91.5 r180 top
C819 "S2P_CC-1.6x0.8x0.8-PX1.6+102" S2P_CC-1.6x0.8x0.8-PX1.6+102 229.5,86.5 r0 top
C820 "S2P_CC-1.6x0.8x0.8-PX1.6+101" S2P_CC-1.6x0.8x0.8-PX1.6+101 233.5,82 r0 top
C821 "S2P_CE-6.6x6.6x5.8-PX7" S2P_CE-6.6x6.6x5.8-PX7 253.5,127 r270 top
C822 "S2P_CE-6.6x6.6x5.8-PX7+1" S2P_CE-6.6x6.6x5.8-PX7+1 193.5,127 r270 top
C823 "S2P_CE-6.6x6.6x5.8-PX7+2" S2P_CE-6.6x6.6x5.8-PX7+2 133.5,127 r270 top
C824 "S2P_CE-6.6x6.6x5.8-PX7+3" S2P_CE-6.6x6.6x5.8-PX7+3 73.5,127 r270 top
C825 "S2P_CC-1.6x0.8x0.8-PX1.6+84" S2P_CC-1.6x0.8x0.8-PX1.6+84 238.5,129 r90 top
C826 "S2P_CC-1.6x0.8x0.8-PX1.6+83" S2P_CC-1.6x0.8x0.8-PX1.6+83 178.5,129 r90 top
C827 "S2P_CC-1.6x0.8x0.8-PX1.6+82" S2P_CC-1.6x0.8x0.8-PX1.6+82 118.5,129 r90 top
C828 "S2P_CC-1.6x0.8x0.8-PX1.6+81" S2P_CC-1.6x0.8x0.8-PX1.6+81 58.5,129 r90 top
C829 "S2P_CC-2x1.25x1.25-PX2+8" S2P_CC-2x1.25x1.25-PX2+8 238.5,125 r270 top
C830 "S2P_CC-2x1.25x1.25-PX2+7" S2P_CC-2x1.25x1.25-PX2+7 178.5,125 r270 top
C831 "S2P_CC-2x1.25x1.25-PX2+6" S2P_CC-2x1.25x1.25-PX2+6 118.5,125 r270 top
C832 "S2P_CC-2x1.25x1.25-PX2+5" S2P_CC-2x1.25x1.25-PX2+5 58.5,125 r270 top
C836 "_CKG57NX7S2A226M500JJ_+3" _CKG57NX7S2A226M500JJ_+3 256.75,95.5 r90 bottom
C837 "_CKG57NX7S2A226M500JJ_" _CKG57NX7S2A226M500JJ_ 250.5,95.5 r90 bottom
C843 "_CGA3E2C0G1H472J080AA_+25" _CGA3E2C0G1H472J080AA_+25 114,37.5 r0 bottom
C869 "_CGA3E2C0G1H472J080AA_+28" _CGA3E2C0G1H472J080AA_+28 63,37.5 r0 bottom
C886 "_CGA3E2C0G1H472J080AA_+3" _CGA3E2C0G1H472J080AA_+3 199.75,22.5 r0 bottom
C887 "_CGA3E2C0G1H472J080AA_+15" _CGA3E2C0G1H472J080AA_+15 189,22.5 r0 bottom
C888 "_CGA3E2C0G1H472J080AA_+22" _CGA3E2C0G1H472J080AA_+22 112,22.5 r0 bottom
C889 "_CGA3E2C0G1H472J080AA_+30" _CGA3E2C0G1H472J080AA_+30 101.25,22.5 r0 bottom
C890 "_CGA3E2C0G1H472J080AA_+26" _CGA3E2C0G1H472J080AA_+26 79.75,22.5 r0 bottom
C891 "_CGA3E2C0G1H472J080AA_+37" _CGA3E2C0G1H472J080AA_+37 69,22.5 r0 bottom
C910 "_CGA3E2X7R1H104K080AA_+17" _CGA3E2X7R1H104K080AA_+17 218,48.75 r0 bottom
C911 "_CGA3E2X7R1H104K080AA_+19" _CGA3E2X7R1H104K080AA_+19 225.5,43.5 r0 bottom
C913 "_CGA3E2C0G1H472J080AA_+12" _CGA3E2C0G1H472J080AA_+12 210.5,22.5 r0 bottom
C914 "_CGA3E2C0G1H472J080AA_+13" _CGA3E2C0G1H472J080AA_+13 218,39 r0 bottom
C915 "_CGA3E2C0G1H472J080AA_+14" _CGA3E2C0G1H472J080AA_+14 225.5,39 r0 bottom
C916 "_CGA3E2X7R1H104K080AA_+16" _CGA3E2X7R1H104K080AA_+16 218,41 r180 bottom
C917 "_CGA3E2X7R1H104K080AA_+18" _CGA3E2X7R1H104K080AA_+18 225.5,41 r180 bottom
C918 "_CGA3E2X7R1H104K080AA_+20" _CGA3E2X7R1H104K080AA_+20 221.75,56.5 r0 bottom
C919 "_CGA3E2X7R1H104K080AA_+21" _CGA3E2X7R1H104K080AA_+21 232.25,66.5 r90 bottom
C920 "_CGA3E2X7R1H104K080AA_+27" _CGA3E2X7R1H104K080AA_+27 174.5,44.75 r0 bottom
C921 "_CGA3E2X7R1H104K080AA_+29" _CGA3E2X7R1H104K080AA_+29 182,39.5 r0 bottom
C923 "_CGA3E2C0G1H472J080AA_+19" _CGA3E2C0G1H472J080AA_+19 178.25,22.5 r0 bottom
C924 "_CGA3E2C0G1H472J080AA_+20" _CGA3E2C0G1H472J080AA_+20 174.5,35 r0 bottom
C925 "_CGA3E2C0G1H472J080AA_+21" _CGA3E2C0G1H472J080AA_+21 182,35 r0 bottom
C926 "_CGA3E2X7R1H104K080AA_+26" _CGA3E2X7R1H104K080AA_+26 174.5,37 r180 bottom
C927 "_CGA3E2X7R1H104K080AA_+28" _CGA3E2X7R1H104K080AA_+28 182,37 r180 bottom
C928 "_CGA3E2X7R1H104K080AA_+30" _CGA3E2X7R1H104K080AA_+30 178.25,51.5 r0 bottom
C929 "_CGA3E2X7R1H104K080AA_+63" _CGA3E2X7R1H104K080AA_+63 204,65 r90 bottom
C930 "_CGA3E2X7R1H104K080AA_+47" _CGA3E2X7R1H104K080AA_+47 77.5,47.25 r0 bottom
C931 "_CGA3E2X7R1H104K080AA_+49" _CGA3E2X7R1H104K080AA_+49 85,42 r0 bottom
C933 "_CGA3E2C0G1H472J080AA_+34" _CGA3E2C0G1H472J080AA_+34 90.5,22.5 r0 bottom
C934 "_CGA3E2C0G1H472J080AA_+35" _CGA3E2C0G1H472J080AA_+35 77.5,37.5 r0 bottom
C935 "_CGA3E2C0G1H472J080AA_+36" _CGA3E2C0G1H472J080AA_+36 85,37.5 r0 bottom
C936 "_CGA3E2X7R1H104K080AA_+46" _CGA3E2X7R1H104K080AA_+46 77.5,39.5 r180 bottom
C937 "_CGA3E2X7R1H104K080AA_+48" _CGA3E2X7R1H104K080AA_+48 85,39.5 r180 bottom
C938 "_CGA3E2X7R1H104K080AA_+50" _CGA3E2X7R1H104K080AA_+50 80.75,56 r0 bottom
C939 "_CGA3E2X7R1H104K080AA_+51" _CGA3E2X7R1H104K080AA_+51 91.25,66 r90 bottom
C940 "_CGA3E2X7R1H104K080AA_+58" _CGA3E2X7R1H104K080AA_+58 34,47.25 r0 bottom
C941 "_CGA3E2X7R1H104K080AA_+60" _CGA3E2X7R1H104K080AA_+60 41.5,42 r0 bottom
C943 "_CGA3E2C0G1H472J080AA_+41" _CGA3E2C0G1H472J080AA_+41 58.25,22.5 r0 bottom
C944 "_CGA3E2C0G1H472J080AA_+42" _CGA3E2C0G1H472J080AA_+42 34,37.5 r0 bottom
C945 "_CGA3E2C0G1H472J080AA_+43" _CGA3E2C0G1H472J080AA_+43 41.5,37.5 r0 bottom
C946 "_CGA3E2X7R1H104K080AA_+57" _CGA3E2X7R1H104K080AA_+57 34,39.5 r180 bottom
C947 "_CGA3E2X7R1H104K080AA_+59" _CGA3E2X7R1H104K080AA_+59 41.5,39.5 r180 bottom
C948 "_CGA3E2X7R1H104K080AA_+61" _CGA3E2X7R1H104K080AA_+61 37.25,56 r0 bottom
C949 "_CGA3E2X7R1H104K080AA_+62" _CGA3E2X7R1H104K080AA_+62 39.5,66 r90 bottom
CN1 "D6P_CN-13.9x4.5x6-PX2-H0.9" D6P_CN-13.9x4.5x6-PX2-H0.9 215,138 r0 top
CN2 "D9P_CN-19.9x4.5x6-PX2-H0.9" D9P_CN-19.9x4.5x6-PX2-H0.9 234,138 r0 top
CN3 "D8P_CN-22.4x5.75x7-PX2.5-H1.1" D8P_CN-22.4x5.75x7-PX2.5-H1.1 248.5,23.5 r0 top
CN4 "D5P_CN-11.9x4.5x6-PX2-H0.9" D5P_CN-11.9x4.5x6-PX2-H0.9 252,138 r0 top
CN5 "D2P_CN-5.9x4.5x6-PX2-H0.9" D2P_CN-5.9x4.5x6-PX2-H0.9 260,127 r270 top
CN6 "D2P_CN-7.4x5.75x7-PX2.5-H1.1" D2P_CN-7.4x5.75x7-PX2.5-H1.1 265,93 r270 top
CN7 "_B3B-XH-A_" _B3B-XH-A_ 265,72 r270 top
CN101 "D6P_CN-13.9x4.5x6-PX2-H0.9" D6P_CN-13.9x4.5x6-PX2-H0.9 162,138 r0 top
CN102 "D9P_CN-19.9x4.5x6-PX2-H0.9" D9P_CN-19.9x4.5x6-PX2-H0.9 182,138 r0 top
CN103 "D8P_CN-22.4x5.75x7-PX2.5-H1.1" D8P_CN-22.4x5.75x7-PX2.5-H1.1 161.5,23.5 r0 top
CN104 "D5P_CN-11.9x4.5x6-PX2-H0.9" D5P_CN-11.9x4.5x6-PX2-H0.9 200,138 r0 top
CN105 "D2P_CN-5.9x4.5x6-PX2-H0.9" D2P_CN-5.9x4.5x6-PX2-H0.9 200,127 r270 top
CN201 "D6P_CN-13.9x4.5x6-PX2-H0.9" D6P_CN-13.9x4.5x6-PX2-H0.9 95,138 r0 top
CN202 "D9P_CN-19.9x4.5x6-PX2-H0.9" D9P_CN-19.9x4.5x6-PX2-H0.9 114,138 r0 top
CN203 "D8P_CN-22.4x5.75x7-PX2.5-H1.1" D8P_CN-22.4x5.75x7-PX2.5-H1.1 128.5,23.5 r0 top
CN204 "D5P_CN-11.9x4.5x6-PX2-H0.9" D5P_CN-11.9x4.5x6-PX2-H0.9 132,138 r0 top
CN205 "D2P_CN-5.9x4.5x6-PX2-H0.9" D2P_CN-5.9x4.5x6-PX2-H0.9 140,127 r270 top
CN208 "_B2P-VH_" _B2P-VH_ 189,25.5 r180 top
CN301 "D6P_CN-13.9x4.5x6-PX2-H0.9" D6P_CN-13.9x4.5x6-PX2-H0.9 43,137.75 r0 top
CN302 "D9P_CN-19.9x4.5x6-PX2-H0.9" D9P_CN-19.9x4.5x6-PX2-H0.9 62,138 r0 top
CN303 "D8P_CN-22.4x5.75x7-PX2.5-H1.1" D8P_CN-22.4x5.75x7-PX2.5-H1.1 41.5,23.5 r0 top
CN304 "D5P_CN-11.9x4.5x6-PX2-H0.9" D5P_CN-11.9x4.5x6-PX2-H0.9 80,138 r0 top
CN305 "D2P_CN-5.9x4.5x6-PX2-H0.9" D2P_CN-5.9x4.5x6-PX2-H0.9 80,127 r270 top
CN307 "_B2P-VH_" _B2P-VH_ 112,25.5 r180 top
CN308 "_B2P-VH_" _B2P-VH_ 101.25,25.5 r180 top
CN400 "S2P_CN-5.08x2.54x9.65-PX2.54" S2P_CN-5.08x2.54x9.65-PX2.54 232.75,77.25 r0 top
CN407 "_B2P-VH_" _B2P-VH_ 79.75,25.5 r180 top
CN408 "_B2P-VH_" _B2P-VH_ 69,25.5 r180 top
CN500 "S2P_CN-5.08x2.54x9.65-PX2.54+1" S2P_CN-5.08x2.54x9.65-PX2.54+1 197,87.5 r0 top
CN501 "S2P_CN-5.08x2.54x9.65-PX2.54+6" S2P_CN-5.08x2.54x9.65-PX2.54+6 250.5,60.75 r90 top
CN502 "_TSW-101-07-G-S_" _TSW-101-07-G-S_ 247,56.5 r0 top
CN503 "S2P_CN-5.08x2.54x9.65-PX2.54+7" S2P_CN-5.08x2.54x9.65-PX2.54+7 256,60.75 r90 top
CN504 "S2P_CN-5.08x2.54x9.65-PX2.54+8" S2P_CN-5.08x2.54x9.65-PX2.54+8 235.5,60.75 r90 top
CN505 "_TSW-101-07-G-S_" _TSW-101-07-G-S_ 232,56.5 r0 top
CN506 "S2P_CN-5.08x2.54x9.65-PX2.54+9" S2P_CN-5.08x2.54x9.65-PX2.54+9 241,60.75 r90 top
CN508 "_B2P-VH_" _B2P-VH_ 232,25.5 r180 top
CN509 "_B2P-VH_" _B2P-VH_ 221.25,25.5 r180 top
CN510 "S2P_CN-5.08x2.54x9.65-PX2.54+2" S2P_CN-5.08x2.54x9.65-PX2.54+2 197.5,77.5 r0 top
CN511 "S2P_CN-5.08x2.54x9.65-PX2.54+10" S2P_CN-5.08x2.54x9.65-PX2.54+10 208,59.75 r90 top
CN512 "_TSW-101-07-G-S_" _TSW-101-07-G-S_ 203.75,55.5 r0 top
CN513 "S2P_CN-5.08x2.54x9.65-PX2.54+11" S2P_CN-5.08x2.54x9.65-PX2.54+11 213.5,59.75 r90 top
CN514 "S2P_CN-5.08x2.54x9.65-PX2.54+12" S2P_CN-5.08x2.54x9.65-PX2.54+12 194.25,59.5 r90 top
CN515 "_TSW-101-07-G-S_" _TSW-101-07-G-S_ 190,55.25 r0 top
CN516 "S2P_CN-5.08x2.54x9.65-PX2.54+13" S2P_CN-5.08x2.54x9.65-PX2.54+13 199.75,59.5 r90 top
CN520 "S2P_CN-5.08x2.54x9.65-PX2.54+3" S2P_CN-5.08x2.54x9.65-PX2.54+3 188,77.5 r0 top
CN530 "S2P_CN-5.08x2.54x9.65-PX2.54+4" S2P_CN-5.08x2.54x9.65-PX2.54+4 178,77.5 r0 top
CN540 "S2P_CN-5.08x2.54x9.65-PX2.54+5" S2P_CN-5.08x2.54x9.65-PX2.54+5 168.5,77.5 r0 top
CN618 "_B2P-VH_" _B2P-VH_ 199.75,25.5 r180 top
CN620 "S14P_CN-17.78x5.08x9.65-PX2.54-PY7.62" S14P_CN-17.78x5.08x9.65-PX2.54-PY7.62 94.75,81.75 r90 top
CN910 "_B2P-VH_" _B2P-VH_ 210.5,25.5 r180 top
CN911 "S2P_CN-5.08x2.54x9.65-PX2.54+14" S2P_CN-5.08x2.54x9.65-PX2.54+14 221.5,60.75 r90 top
CN912 "_TSW-101-07-G-S_" _TSW-101-07-G-S_ 218,56.5 r0 top
CN913 "S2P_CN-5.08x2.54x9.65-PX2.54+15" S2P_CN-5.08x2.54x9.65-PX2.54+15 227,60.75 r90 top
CN920 "_B2P-VH_" _B2P-VH_ 178.25,25.25 r180 top
CN921 "S2P_CN-5.08x2.54x9.65-PX2.54+16" S2P_CN-5.08x2.54x9.65-PX2.54+16 179,55.5 r90 top
CN922 "_TSW-101-07-G-S_" _TSW-101-07-G-S_ 174.5,51.5 r0 top
CN923 "S2P_CN-5.08x2.54x9.65-PX2.54+17" S2P_CN-5.08x2.54x9.65-PX2.54+17 184.5,55.5 r90 top
CN924 "S2P_CN-5.08x2.54x9.65-PX2.54+18" S2P_CN-5.08x2.54x9.65-PX2.54+18 109.5,60.25 r90 top
CN925 "_TSW-101-07-G-S_" _TSW-101-07-G-S_ 106,56 r0 top
CN926 "S2P_CN-5.08x2.54x9.65-PX2.54+19" S2P_CN-5.08x2.54x9.65-PX2.54+19 115,60.25 r90 top
CN927 "S2P_CN-5.08x2.54x9.65-PX2.54+20" S2P_CN-5.08x2.54x9.65-PX2.54+20 95,60.25 r90 top
CN928 "_TSW-101-07-G-S_" _TSW-101-07-G-S_ 91.5,56 r0 top
CN929 "S2P_CN-5.08x2.54x9.65-PX2.54+21" S2P_CN-5.08x2.54x9.65-PX2.54+21 100.5,60.25 r90 top
CN930 "S2P_CN-5.08x2.54x9.65-PX2.54+22" S2P_CN-5.08x2.54x9.65-PX2.54+22 66,60.25 r90 top
CN931 "_TSW-101-07-G-S_" _TSW-101-07-G-S_ 62.5,56 r0 top
CN932 "S2P_CN-5.08x2.54x9.65-PX2.54+23" S2P_CN-5.08x2.54x9.65-PX2.54+23 71.5,60.25 r90 top
CN933 "S2P_CN-5.08x2.54x9.65-PX2.54+24" S2P_CN-5.08x2.54x9.65-PX2.54+24 51.5,60.25 r90 top
CN934 "_TSW-101-07-G-S_" _TSW-101-07-G-S_ 48,56 r0 top
CN935 "S2P_CN-5.08x2.54x9.65-PX2.54+25" S2P_CN-5.08x2.54x9.65-PX2.54+25 57,60.25 r90 top
CN936 "_B2P-VH_" _B2P-VH_ 90.5,25.5 r180 top
CN937 "S2P_CN-5.08x2.54x9.65-PX2.54+26" S2P_CN-5.08x2.54x9.65-PX2.54+26 80.5,60.25 r90 top
CN938 "_TSW-101-07-G-S_" _TSW-101-07-G-S_ 77,56 r0 top
CN939 "S2P_CN-5.08x2.54x9.65-PX2.54+27" S2P_CN-5.08x2.54x9.65-PX2.54+27 86,60.25 r90 top
CN940 "_B2P-VH_" _B2P-VH_ 58.25,25.5 r180 top
CN941 "S2P_CN-5.08x2.54x9.65-PX2.54+28" S2P_CN-5.08x2.54x9.65-PX2.54+28 37,60.25 r90 top
CN942 "_TSW-101-07-G-S_" _TSW-101-07-G-S_ 33.5,56 r0 top
CN943 "S2P_CN-5.08x2.54x9.65-PX2.54+29" S2P_CN-5.08x2.54x9.65-PX2.54+29 42.5,60.25 r90 top
CN945 "S2P_CN-5.08x2.54x9.65-PX2.54+30" S2P_CN-5.08x2.54x9.65-PX2.54+30 259.375,82.125 r270 top
CN952 "_TSW-101-07-G-S_" _TSW-101-07-G-S_ 245.125,68.625 r0 top
CN953 "_TSW-101-07-G-S_" _TSW-101-07-G-S_ 246.75,80.75 r0 top
CN954 "_TSW-101-07-G-S_" _TSW-101-07-G-S_ 255.375,88 r0 top
CN955 "_TSW-101-07-G-S_" _TSW-101-07-G-S_ 250.75,100.5 r0 top
CN956 "_TSW-101-07-G-S_" _TSW-101-07-G-S_ 235,102 r0 top
CN957 "_TSW-101-07-G-S_" _TSW-101-07-G-S_ 170.375,37.625 r0 top
CN958 "_TSW-101-07-G-S_" _TSW-101-07-G-S_ 160.125,37.875 r0 top
CN959 "_TSW-101-07-G-S_" _TSW-101-07-G-S_ 154.375,38.6 r0 top
CN960 "_HW-1-S_" _HW-1-S_ 253.5,119.5 r0 top
CN961 "_TSW-101-07-G-S_" _TSW-101-07-G-S_ 246.5,102 r0 top
CN962 "S2P_CN-5.08x2.54x9.65-PX2.54+31" S2P_CN-5.08x2.54x9.65-PX2.54+31 224.5,87.75 r0 top
CN963 "_TSW-101-07-G-S_" _TSW-101-07-G-S_ 151.875,32.625 r0 top
CN964 "_TSW-101-07-G-S_" _TSW-101-07-G-S_ 150.5,44 r0 top
CP1 "_Direct_In_PAD-D2_" _Direct_In_PAD-D2_ 221.75,132.5 r0 top
CP2 "_Direct_In_PAD-D2_+1" _Direct_In_PAD-D2_+1 221.75,105.5 r0 top
CP3 "_Direct_In_PAD-D2_+2" _Direct_In_PAD-D2_+2 241.25,121.5 r0 top
CP4 "_Direct_In_PAD-D2_+3" _Direct_In_PAD-D2_+3 237.25,105.5 r0 top
CP5 "_Direct_In_PAD-D2_+4" _Direct_In_PAD-D2_+4 161.75,132.5 r0 top
CP6 "_Direct_In_PAD-D2_+5" _Direct_In_PAD-D2_+5 161.75,105.5 r0 top
CP7 "_Direct_In_PAD-D2_+6" _Direct_In_PAD-D2_+6 181.25,121.5 r0 top
CP8 "_Direct_In_PAD-D2_+7" _Direct_In_PAD-D2_+7 177.25,105.5 r0 top
CP9 "_Direct_In_PAD-D2_+8" _Direct_In_PAD-D2_+8 101.75,132.5 r0 top
CP10 "_Direct_In_PAD-D2_+9" _Direct_In_PAD-D2_+9 101.75,105.5 r0 top
CP11 "_Direct_In_PAD-D2_+10" _Direct_In_PAD-D2_+10 121.25,121.5 r0 top
CP12 "_Direct_In_PAD-D2_+11" _Direct_In_PAD-D2_+11 117.25,105.5 r0 top
CP13 "_Direct_In_PAD-D2_+12" _Direct_In_PAD-D2_+12 41.75,132.5 r0 top
CP14 "_Direct_In_PAD-D2_+13" _Direct_In_PAD-D2_+13 41.75,105.5 r0 top
CP15 "_Direct_In_PAD-D2_+14" _Direct_In_PAD-D2_+14 61.25,121.5 r0 top
CP16 "_Direct_In_PAD-D2_+15" _Direct_In_PAD-D2_+15 57.25,105.5 r0 top
D620 "S2P_D-1.2x0.8x0.6-PX1.6" S2P_D-1.2x0.8x0.6-PX1.6 135.5,42.5 r90 bottom
D650 "S2P_ZD-2x1.4x0.6-PX2.5" S2P_ZD-2x1.4x0.6-PX2.5 151.875,37.125 r270 bottom
D711 "_1SS362FV_+9" _1SS362FV_+9 250.75,56.5 r270 top
D712 "_1SS362FV_" _1SS362FV_ 235.75,56.5 r270 top
D713 "_1SS362FV_+10" _1SS362FV_+10 235.5,66.5 r0 top
D721 "_1SS362FV_+1" _1SS362FV_+1 207.5,55.5 r270 top
D722 "_1SS362FV_+2" _1SS362FV_+2 193.75,55.25 r270 top
D731 "_1SS362FV_+3" _1SS362FV_+3 109.75,56 r270 top
D732 "_1SS362FV_+4" _1SS362FV_+4 95.25,56 r270 top
D741 "_1SS362FV_+5" _1SS362FV_+5 66.25,56 r270 top
D742 "_1SS362FV_+6" _1SS362FV_+6 51.75,56 r270 top
D800 "S2P_D-3.8x2.4x1-PX4.7+4" S2P_D-3.8x2.4x1-PX4.7+4 258,69.5 r180 top
D801 "S2P_D-3.8x2.4x1-PX4.7+6" S2P_D-3.8x2.4x1-PX4.7+6 239.75,28.5 r270 bottom
D802 "S2P_D-3.8x2.4x1-PX4.7+5" S2P_D-3.8x2.4x1-PX4.7+5 152.75,28.5 r270 bottom
D803 "S2P_D-3.8x2.4x1-PX4.7+3" S2P_D-3.8x2.4x1-PX4.7+3 119.75,28.5 r270 bottom
D804 "S2P_D-3.8x2.4x1-PX4.7" S2P_D-3.8x2.4x1-PX4.7 32.75,28.5 r270 bottom
D805 "S2P_D-3.8x2.4x1-PX4.7+8" S2P_D-3.8x2.4x1-PX4.7+8 259,95.5 r270 top
D806 "S2P_D-3.8x2.4x1-PX4.7+1" S2P_D-3.8x2.4x1-PX4.7+1 253.625,76.375 r90 top
D807 "S2P_D-3.8x2.4x1-PX4.7+7" S2P_D-3.8x2.4x1-PX4.7+7 236.5,96.75 r270 bottom
D808 "S2P_D-2.6x1.6x1-PX3.5" S2P_D-2.6x1.6x1-PX3.5 232,71.5 r0 top
D809 "S2P_D-1.2x0.8x0.6-PX1.6+2" S2P_D-1.2x0.8x0.6-PX1.6+2 240.75,73 r180 bottom
D810 "S2P_D-1.2x0.8x0.6-PX1.6+1" S2P_D-1.2x0.8x0.6-PX1.6+1 244.5,75 r180 bottom
D811 "S2P_D-3.8x2.4x1-PX4.7+2" S2P_D-3.8x2.4x1-PX4.7+2 244.75,86.75 r90 top
D812 "_1SS362FV_+11" _1SS362FV_+11 207.25,65 r0 top
D813 "_1SS362FV_+7" _1SS362FV_+7 94.5,66 r0 top
D912 "_1SS362FV_+8" _1SS362FV_+8 42.75,66 r0 top
DS510 "_KB_DELPS2.12_" _KB_DELPS2.12_ 199,71.25 r90 top
DS511 "_KT_DELQS1.12_" _KT_DELQS1.12_ 196,71.25 r270 top
DS512 "_KT_DELQS1.12_+1" _KT_DELQS1.12_+1 199,65 r90 top
DS513 "_KS_DELPS1.22_" _KS_DELPS1.22_ 196,65 r270 top
DS520 "_KB_DELPS2.12_+2" _KB_DELPS2.12_+2 189.5,71.25 r90 top
DS521 "_KT_DELQS1.12_+5" _KT_DELQS1.12_+5 186.5,71.25 r270 top
DS522 "_KT_DELQS1.12_+2" _KT_DELQS1.12_+2 189.5,65 r90 top
DS523 "_KS_DELPS1.22_+1" _KS_DELPS1.22_+1 186.5,65 r270 top
DS530 "_KB_DELPS2.12_+3" _KB_DELPS2.12_+3 179.5,71.25 r90 top
DS531 "_KT_DELQS1.12_+7" _KT_DELQS1.12_+7 176.5,71.25 r270 top
DS532 "_KT_DELQS1.12_+6" _KT_DELQS1.12_+6 179.5,65 r90 top
DS533 "_KS_DELPS1.22_+3" _KS_DELPS1.22_+3 176.5,65 r270 top
DS540 "_KB_DELPS2.12_+1" _KB_DELPS2.12_+1 170,71.25 r90 top
DS541 "_KT_DELQS1.12_+4" _KT_DELQS1.12_+4 167,71.25 r270 top
DS542 "_KT_DELQS1.12_+3" _KT_DELQS1.12_+3 169.5,65 r90 top
DS543 "_KS_DELPS1.22_+2" _KS_DELPS1.22_+2 166.5,65 r270 top
IC106 "S5P_U-2x1.25x1-PX0.65-PY2.1" S5P_U-2x1.25x1-PX0.65-PY2.1 183.25,87.75 r270 top
IC600 "_TMS320F28377SPTP_" _TMS320F28377SPTP_ 140,74 r180 top
IC601 "S14P_U-8.65x3.9x1.75-PX1.27-PY6" S14P_U-8.65x3.9x1.75-PX1.27-PY6 105,83.5 r90 top
IC602 "_LM4040QCEM3-3.0_" _LM4040QCEM3-3.0_ 113.25,84.25 r0 bottom
IC620 "S6P_U-2.9x1.6x1.1-PX0.95-PY2.8" S6P_U-2.9x1.6x1.1-PX0.95-PY2.8 140.5,46 r0 top
IC621 "S6P_U-2.9x1.6x1.1-PX0.95-PY2.8+1" S6P_U-2.9x1.6x1.1-PX0.95-PY2.8+1 132.5,42.5 r180 top
IC650 "S8P_U-1.2x2.1x0.6-PX1.6-PY0.5" S8P_U-1.2x2.1x0.6-PX1.6-PY0.5 167.125,40.625 r270 top
IC651 "S11P_U-3x3x0.9-PX3-PY0.5" S11P_U-3x3x0.9-PX3-PY0.5 144.25,37.75 r180 top
IC710 "_TLVH431AQDBVRQ1_" _TLVH431AQDBVRQ1_ 240,44.75 r180 top
IC711 "_TLVH431AQDBVRQ1_+1" _TLVH431AQDBVRQ1_+1 247.5,44.75 r180 top
IC712 "_TLVH431AQDBVRQ1_+2" _TLVH431AQDBVRQ1_+2 255,44.75 r180 top
IC713 "_INA290A2QDCKRQ1_+22" _INA290A2QDCKRQ1_+22 247.5,40 r180 top
IC714 "_INA290A2QDCKRQ1_+23" _INA290A2QDCKRQ1_+23 255,40 r180 top
IC715 "_TS5A3159QDBVRQ1_" _TS5A3159QDBVRQ1_ 251.25,49.75 r180 top
IC716 "_INA290A2QDCKRQ1_" _INA290A2QDCKRQ1_ 232.5,40 r180 top
IC717 "_INA290A2QDCKRQ1_+1" _INA290A2QDCKRQ1_+1 240,40 r180 top
IC718 "_TS5A3159QDBVRQ1_+1" _TS5A3159QDBVRQ1_+1 236.25,49.75 r180 top
IC719 "_TLVH431AQDBVRQ1_+3" _TLVH431AQDBVRQ1_+3 232.5,44.75 r180 top
IC720 "_TLVH431AQDBVRQ1_+4" _TLVH431AQDBVRQ1_+4 196.5,43.75 r180 top
IC721 "_TLVH431AQDBVRQ1_+5" _TLVH431AQDBVRQ1_+5 203.5,43.75 r180 top
IC722 "_TLVH431AQDBVRQ1_+6" _TLVH431AQDBVRQ1_+6 211,43.75 r180 top
IC723 "_INA290A2QDCKRQ1_+2" _INA290A2QDCKRQ1_+2 203.5,39 r180 top
IC724 "_INA290A2QDCKRQ1_+3" _INA290A2QDCKRQ1_+3 211,39 r180 top
IC725 "_TS5A3159QDBVRQ1_+2" _TS5A3159QDBVRQ1_+2 207.25,48.75 r180 top
IC726 "_INA290A2QDCKRQ1_+4" _INA290A2QDCKRQ1_+4 189,39 r180 top
IC727 "_INA290A2QDCKRQ1_+5" _INA290A2QDCKRQ1_+5 196.5,39 r180 top
IC728 "_TS5A3159QDBVRQ1_+3" _TS5A3159QDBVRQ1_+3 192.75,48.75 r180 top
IC729 "_TLVH431AQDBVRQ1_+7" _TLVH431AQDBVRQ1_+7 189,43.75 r180 top
IC730 "_TLVH431AQDBVRQ1_+8" _TLVH431AQDBVRQ1_+8 99.5,43.25 r180 top
IC731 "_TLVH431AQDBVRQ1_+9" _TLVH431AQDBVRQ1_+9 106.5,43.25 r180 top
IC732 "_TLVH431AQDBVRQ1_+10" _TLVH431AQDBVRQ1_+10 114,43.25 r180 top
IC733 "_INA290A2QDCKRQ1_+6" _INA290A2QDCKRQ1_+6 106.5,38.5 r180 top
IC734 "_INA290A2QDCKRQ1_+7" _INA290A2QDCKRQ1_+7 114,38.5 r180 top
IC735 "_TS5A3159QDBVRQ1_+4" _TS5A3159QDBVRQ1_+4 110.25,48.25 r180 top
IC736 "_INA290A2QDCKRQ1_+8" _INA290A2QDCKRQ1_+8 92,38.5 r180 top
IC737 "_INA290A2QDCKRQ1_+9" _INA290A2QDCKRQ1_+9 99.5,38.5 r180 top
IC738 "_TS5A3159QDBVRQ1_+5" _TS5A3159QDBVRQ1_+5 95.75,48.25 r180 top
IC739 "_TLVH431AQDBVRQ1_+11" _TLVH431AQDBVRQ1_+11 92,43.25 r180 top
IC740 "_TLVH431AQDBVRQ1_+12" _TLVH431AQDBVRQ1_+12 56,43.25 r180 top
IC741 "_TLVH431AQDBVRQ1_+13" _TLVH431AQDBVRQ1_+13 63,43.25 r180 top
IC742 "_TLVH431AQDBVRQ1_+14" _TLVH431AQDBVRQ1_+14 70.5,43.25 r180 top
IC743 "_INA290A2QDCKRQ1_+10" _INA290A2QDCKRQ1_+10 63,38.5 r180 top
IC744 "_INA290A2QDCKRQ1_+11" _INA290A2QDCKRQ1_+11 70.5,38.5 r180 top
IC745 "_TS5A3159QDBVRQ1_+6" _TS5A3159QDBVRQ1_+6 66.75,48.25 r180 top
IC746 "_INA290A2QDCKRQ1_+12" _INA290A2QDCKRQ1_+12 48.5,38.5 r180 top
IC747 "_INA290A2QDCKRQ1_+13" _INA290A2QDCKRQ1_+13 56,38.5 r180 top
IC748 "_TS5A3159QDBVRQ1_+7" _TS5A3159QDBVRQ1_+7 52.25,48.25 r180 top
IC749 "_TLVH431AQDBVRQ1_+15" _TLVH431AQDBVRQ1_+15 48.5,43.25 r180 top
IC800 "S8P_U-4.9x3.9x1.68-PX1.27-PY6" S8P_U-4.9x3.9x1.68-PX1.27-PY6 243.125,73.625 r90 top
IC801 "S15P_U-4.4x5x1.2-PX6.4-PY0.65" S15P_U-4.4x5x1.2-PX6.4-PY0.65 239,96.125 r0 top
IC802 "S7P_U-3x3x0.75-PX0.95-PY3-1" S7P_U-3x3x0.75-PX0.95-PY3-1 250.75,96.5 r90 top
IC803 "S3P_U-6.53x3.43x1.8-PX2.3-PY7+3" S3P_U-6.53x3.43x1.8-PX2.3-PY7+3 244.5,127 r270 top
IC804 "S3P_U-6.53x3.43x1.8-PX2.3-PY7+2" S3P_U-6.53x3.43x1.8-PX2.3-PY7+2 184.5,127 r270 top
IC805 "S3P_U-6.53x3.43x1.8-PX2.3-PY7+1" S3P_U-6.53x3.43x1.8-PX2.3-PY7+1 124.5,127 r270 top
IC806 "S3P_U-6.53x3.43x1.8-PX2.3-PY7" S3P_U-6.53x3.43x1.8-PX2.3-PY7 64.5,127 r270 top
IC807 "S5P_U-2x1.25x1-PX0.65-PY2.1+1" S5P_U-2x1.25x1-PX0.65-PY2.1+1 178.25,87.75 r270 top
IC808 "S5P_U-2x1.25x1-PX0.65-PY2.1+2" S5P_U-2x1.25x1-PX0.65-PY2.1+2 168.25,87.75 r270 top
IC809 "S5P_U-2x1.25x1-PX0.65-PY2.1+3" S5P_U-2x1.25x1-PX0.65-PY2.1+3 173.25,87.75 r270 top
IC811 "_TLVH431AQDBVRQ1_+16" _TLVH431AQDBVRQ1_+16 218,44.75 r180 top
IC812 "_TLVH431AQDBVRQ1_+17" _TLVH431AQDBVRQ1_+17 225.5,44.75 r180 top
IC813 "_INA290A2QDCKRQ1_+14" _INA290A2QDCKRQ1_+14 218,40 r180 top
IC814 "_INA290A2QDCKRQ1_+15" _INA290A2QDCKRQ1_+15 225.5,40 r180 top
IC815 "_TS5A3159QDBVRQ1_+8" _TS5A3159QDBVRQ1_+8 221.75,49.75 r180 top
IC816 "_TS5A3159QDBVRQ1_+9" _TS5A3159QDBVRQ1_+9 232.25,66.5 r0 top
IC817 "_TLVH431AQDBVRQ1_+18" _TLVH431AQDBVRQ1_+18 174.5,40.75 r180 top
IC818 "_TLVH431AQDBVRQ1_+19" _TLVH431AQDBVRQ1_+19 182,40.75 r180 top
IC819 "_INA290A2QDCKRQ1_+16" _INA290A2QDCKRQ1_+16 174.5,36 r180 top
IC820 "_INA290A2QDCKRQ1_+17" _INA290A2QDCKRQ1_+17 182,36 r180 top
IC821 "_TS5A3159QDBVRQ1_+10" _TS5A3159QDBVRQ1_+10 178.25,45.75 r180 top
IC822 "_TS5A3159QDBVRQ1_+15" _TS5A3159QDBVRQ1_+15 204,65 r0 top
IC823 "_TLVH431AQDBVRQ1_+20" _TLVH431AQDBVRQ1_+20 77.5,43.25 r180 top
IC824 "_TLVH431AQDBVRQ1_+21" _TLVH431AQDBVRQ1_+21 85,43.25 r180 top
IC825 "_INA290A2QDCKRQ1_+18" _INA290A2QDCKRQ1_+18 77.5,38.5 r180 top
IC826 "_INA290A2QDCKRQ1_+19" _INA290A2QDCKRQ1_+19 85,38.5 r180 top
IC827 "_TS5A3159QDBVRQ1_+11" _TS5A3159QDBVRQ1_+11 81.25,48.25 r180 top
IC828 "_TS5A3159QDBVRQ1_+12" _TS5A3159QDBVRQ1_+12 91.25,66 r0 top
IC829 "_TLVH431AQDBVRQ1_+22" _TLVH431AQDBVRQ1_+22 34,43.25 r180 top
IC830 "_TLVH431AQDBVRQ1_+23" _TLVH431AQDBVRQ1_+23 41.5,43.25 r180 top
IC831 "_INA290A2QDCKRQ1_+20" _INA290A2QDCKRQ1_+20 34,38.5 r180 top
IC832 "_INA290A2QDCKRQ1_+21" _INA290A2QDCKRQ1_+21 41.5,38.5 r180 top
IC833 "_TS5A3159QDBVRQ1_+13" _TS5A3159QDBVRQ1_+13 37.75,48.25 r180 top
IC834 "_TS5A3159QDBVRQ1_+14" _TS5A3159QDBVRQ1_+14 39.5,66 r0 top
J801 "_TLRZ1JTTD_" _TLRZ1JTTD_ 255.5,92.5 r0 top
J802 "_TLRZ1JTTD_+1" _TLRZ1JTTD_+1 220.5,89.5 r270 top
J803 "_TLRZ1JTTD_+2" _TLRZ1JTTD_+2 157.125,46.125 r270 top
J804 "_TLRZ1JTTD_+13" _TLRZ1JTTD_+13 135.5,34.5 r270 bottom
J805 "_TLRZ1JTTD_+21" _TLRZ1JTTD_+21 137.5,43 r90 bottom
J806 "_TLRZ1JTTD_+17" _TLRZ1JTTD_+17 221.75,121 r90 top
J807 "_TLRZ1JTTD_+18" _TLRZ1JTTD_+18 221.75,117 r270 top
J808 "_TLRZ1JTTD_+3" _TLRZ1JTTD_+3 161.75,121 r90 top
J809 "_TLRZ1JTTD_+4" _TLRZ1JTTD_+4 161.75,117 r270 top
J810 "_TLRZ1JTTD_+5" _TLRZ1JTTD_+5 101.75,121 r90 top
J811 "_TLRZ1JTTD_+6" _TLRZ1JTTD_+6 101.75,117 r270 top
J812 "_TLRZ1JTTD_+7" _TLRZ1JTTD_+7 41.75,121 r90 top
J813 "_TLRZ1JTTD_+8" _TLRZ1JTTD_+8 41.75,117 r270 top
J814 "_TLRZ1JTTD_+9" _TLRZ1JTTD_+9 237.25,121 r90 top
J817 "_TLRZ1JTTD_+10" _TLRZ1JTTD_+10 177.25,121 r90 top
J818 "_TLRZ1JTTD_+20" _TLRZ1JTTD_+20 248.375,84.625 r180 top
J820 "_TLRZ1JTTD_+11" _TLRZ1JTTD_+11 117.25,121 r90 top
J823 "_TLRZ1JTTD_+12" _TLRZ1JTTD_+12 57.25,121 r90 top
J826 "_TLRZ1JTTD_+14" _TLRZ1JTTD_+14 156.125,42.125 r180 top
J827 "_TLRZ1JTTD_+19" _TLRZ1JTTD_+19 113.25,79 r180 bottom
J828 "_TLRZ1JTTD_+15" _TLRZ1JTTD_+15 246.75,92.25 r90 top
J829 "_TLRZ1JTTD_+16" _TLRZ1JTTD_+16 135.5,38.5 r270 bottom
L650 "S2P_L-3.2x3.5x2-PX1.78" S2P_L-3.2x3.5x2-PX1.78 163.375,43.125 r180 top
L651 "S2P_L-3x3x1.5-PX3+1" S2P_L-3x3x1.5-PX3+1 139.25,35 r90 bottom
L652 "S2P_L-2x1.25x0.85-PX2+2" S2P_L-2x1.25x0.85-PX2+2 109.75,99 r270 bottom
L653 "S2P_L-2x1.25x0.85-PX2" S2P_L-2x1.25x0.85-PX2 124,44.75 r180 bottom
L654 "S2P_L-2x1.25x0.85-PX2+1" S2P_L-2x1.25x0.85-PX2+1 125.5,99 r270 bottom
L656 "S2P_L-3x3x1.5-PX3" S2P_L-3x3x1.5-PX3 141,42.5 r270 bottom
L800 "S2P_L-6.3x6x4.5-PX6.3" S2P_L-6.3x6x4.5-PX6.3 250.625,68.875 r90 top
L801 "S2P_L-12x12x7.8-PY12" S2P_L-12x12x7.8-PY12 225.5,98 r90 top
L802 "S2P_L-12.5x12.1x5.5-PX12.5" S2P_L-12.5x12.1x5.5-PX12.5 214,126 r180 top
L803 "S2P_L-12.5x12.1x5.5-PX12.5+1" S2P_L-12.5x12.1x5.5-PX12.5+1 154,126 r180 top
L804 "S2P_L-12.5x12.1x5.5-PX12.5+2" S2P_L-12.5x12.1x5.5-PX12.5+2 94,126 r180 top
L805 "S2P_L-12.5x12.1x5.5-PX12.5+3" S2P_L-12.5x12.1x5.5-PX12.5+3 34,126 r180 top
L806 "S2P_L-12.5x12.1x5.5-PX12.5+4" S2P_L-12.5x12.1x5.5-PX12.5+4 214,112 r180 top
L807 "S2P_L-12.5x12.1x5.5-PX12.5+5" S2P_L-12.5x12.1x5.5-PX12.5+5 154,112 r180 top
L808 "S2P_L-12.5x12.1x5.5-PX12.5+6" S2P_L-12.5x12.1x5.5-PX12.5+6 94,112 r180 top
L809 "S2P_L-12.5x12.1x5.5-PX12.5+7" S2P_L-12.5x12.1x5.5-PX12.5+7 34,112 r180 top
L810 "S2P_L-12.5x12.1x5.5-PX12.5+8" S2P_L-12.5x12.1x5.5-PX12.5+8 229.5,126 r180 top
L811 "S2P_L-12.5x12.1x5.5-PX12.5+9" S2P_L-12.5x12.1x5.5-PX12.5+9 229.5,112 r180 top
L812 "S2P_L-12.5x12.1x5.5-PX12.5+10" S2P_L-12.5x12.1x5.5-PX12.5+10 245,112 r0 top
L813 "S2P_L-12.5x12.1x5.5-PX12.5+11" S2P_L-12.5x12.1x5.5-PX12.5+11 169.5,126 r180 top
L814 "S2P_L-12.5x12.1x5.5-PX12.5+12" S2P_L-12.5x12.1x5.5-PX12.5+12 169.5,112 r180 top
L815 "S2P_L-12.5x12.1x5.5-PX12.5+13" S2P_L-12.5x12.1x5.5-PX12.5+13 185,112 r0 top
L816 "S2P_L-12.5x12.1x5.5-PX12.5+14" S2P_L-12.5x12.1x5.5-PX12.5+14 109.5,126 r180 top
L817 "S2P_L-12.5x12.1x5.5-PX12.5+15" S2P_L-12.5x12.1x5.5-PX12.5+15 109.5,112 r180 top
L818 "S2P_L-12.5x12.1x5.5-PX12.5+16" S2P_L-12.5x12.1x5.5-PX12.5+16 125,112 r0 top
L819 "S2P_L-12.5x12.1x5.5-PX12.5+17" S2P_L-12.5x12.1x5.5-PX12.5+17 49.5,126 r180 top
